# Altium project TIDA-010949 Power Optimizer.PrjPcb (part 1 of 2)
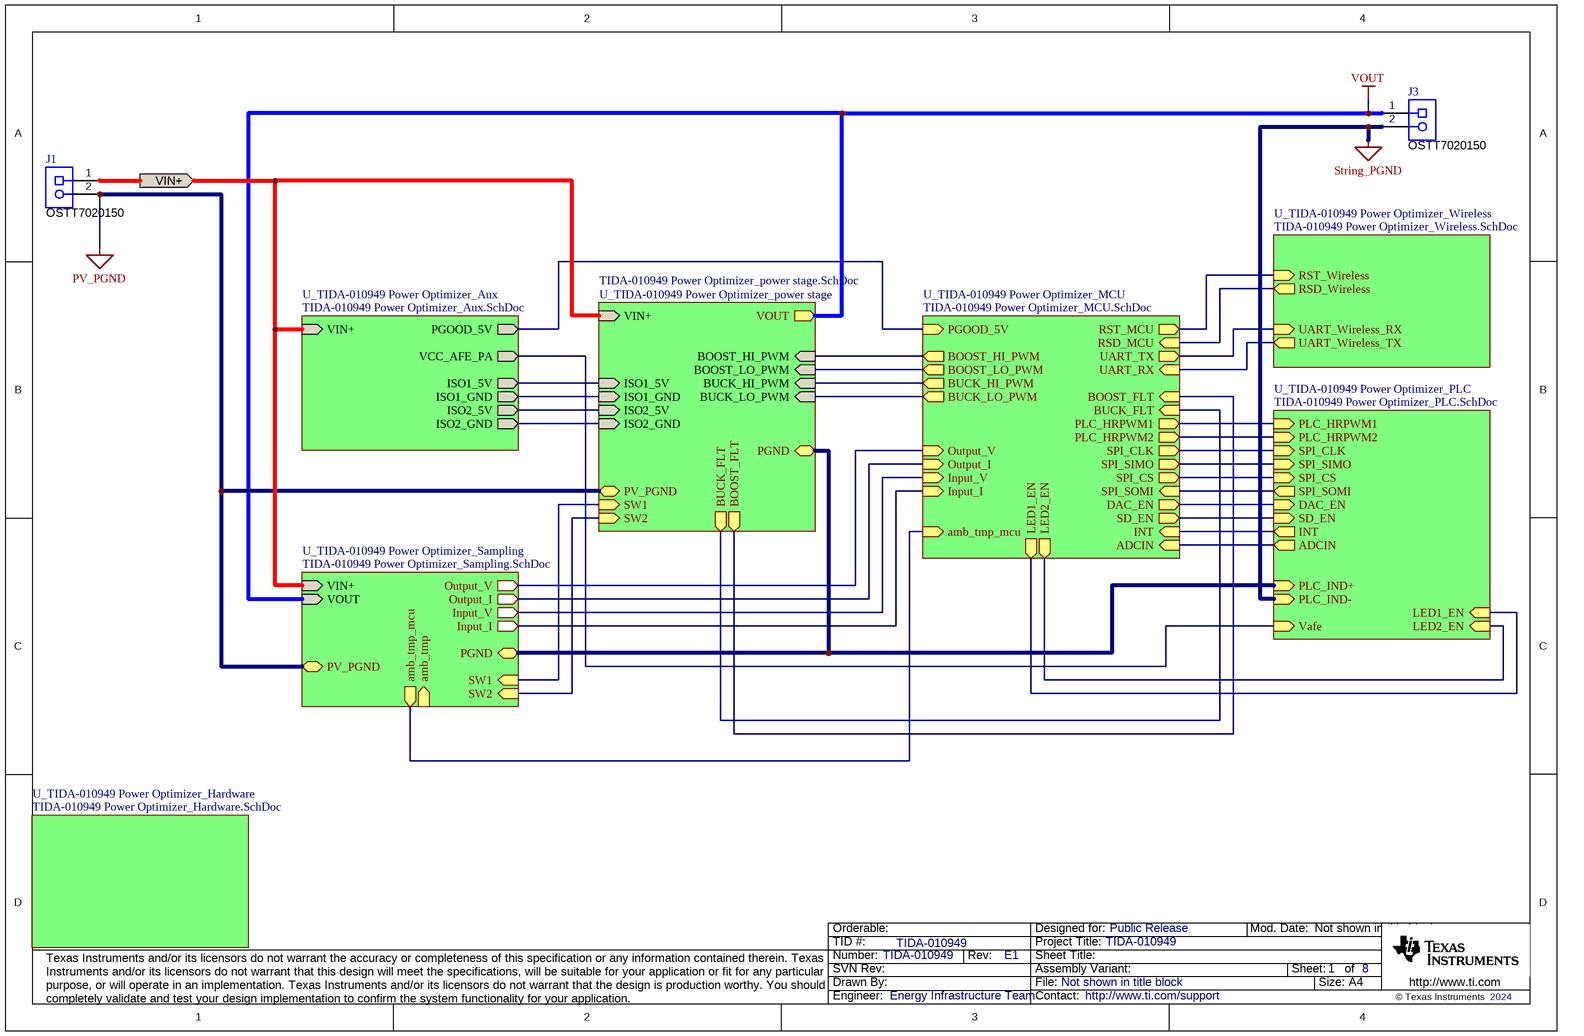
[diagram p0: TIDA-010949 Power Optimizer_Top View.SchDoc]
CopyrightYear: 2024; PCB_Layout: Energy Infrastructure Team; PCB_Rev: E1; PRJ_Customer: Public Release; PRJ_Engineer: Energy Infrastructure Team; PRJ_Number: TIDA-010949; PRJ_Title: TIDA-010949; SCH_Rev: E1; TechSupport: http://www.ti.com/support; TID: TIDA-010949
8 sheets, 266 parts. Net scope: hierarchical (ports join the sheet entries above them; power ports are global).
Board file: TIDA-010949 Power Optimizer.PcbDoc
Sheets:
  TIDA-010949 Power Optimizer_Top View.SchDoc
    U_TIDA-010949 Power Optimizer_Aux = TIDA-010949 Power Optimizer_Aux.SchDoc
    U_TIDA-010949 Power Optimizer_MCU = TIDA-010949 Power Optimizer_MCU.SchDoc
    U_TIDA-010949 Power Optimizer_PLC = TIDA-010949 Power Optimizer_PLC.SchDoc
    U_TIDA-010949 Power Optimizer_Wireless = TIDA-010949 Power Optimizer_Wireless.SchDoc
    U_TIDA-010949 Power Optimizer_Hardware = TIDA-010949 Power Optimizer_Hardware.SchDoc
    U_TIDA-010949 Power Optimizer_Sampling = TIDA-010949 Power Optimizer_Sampling.SchDoc
    U_TIDA-010949 Power Optimizer_power stage = TIDA-010949 Power Optimizer_power stage.SchDoc

## Sheet TIDA-010949 Power Optimizer_Top View.SchDoc
size A4; Date: Not shown in title block; ApprovedBy: Not shown in title block; CheckedBy: Not shown in title block; Author: Not shown in title block; CompanyName: Not shown in title block; Engineer: Not shown in title block; Organization: Not shown in title block; Address1: Not shown in title block; Address2: Not shown in title block; Address3: Not shown in title block; Address4: Not shown in title block; DocumentNumber: 1; Revision: Use project parameter SCH_Rev; SheetNumber: 1; SheetTotal: 8; PageSetup: Record=PageOptions¦CenterHorizontal=True¦CenterVertical=True¦PrintScale=0.93¦XCorrection=1.00¦YCorrection=1.00¦PrintKind=0¦BorderSize=5000000¦LeftOffset=0¦BottomOffset=0¦Orientation=2¦PaperLength=1000¦PaperWidth=1000¦Scale=100¦PaperSource=15¦PrintQuality=600¦MediaType=1¦DitherType=10¦PaperKind=Letter¦PrintScaleMode=1

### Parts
J1  OSTT7020150  [On-Shore_OSTT7020150]
J3  OSTT7020150  [On-Shore_OSTT7020150]

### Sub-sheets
U_TIDA-010949 Power Optimizer_Aux = TIDA-010949 Power Optimizer_Aux.SchDoc: VIN+ (in), PGOOD_5V (out), VCC_AFE_PA (out), ISO1_5V (out), ISO1_GND (out), ISO2_5V (out), ISO2_GND (out)
U_TIDA-010949 Power Optimizer_Hardware = TIDA-010949 Power Optimizer_Hardware.SchDoc: no entries
U_TIDA-010949 Power Optimizer_MCU = TIDA-010949 Power Optimizer_MCU.SchDoc: Output_I (in), Input_I (in), Input_V (in), Output_V (in), PGOOD_5V (in), BUCK_HI_PWM (out), BUCK_LO_PWM (out), BOOST_HI_PWM (out), BOOST_LO_PWM (out), UART_TX (out), PLC_HRPWM1 (out), PLC_HRPWM2 (out), SPI_CLK (out), SPI_SIMO (out), SPI_CS (out), SPI_SOMI (in), DAC_EN (out), SD_EN (out), INT (in), ADCIN (in), LED1_EN (out), LED2_EN (out), UART_RX (in), RSD_MCU (in), RST_MCU (out), amb_tmp_mcu (in), BOOST_FLT (in), BUCK_FLT (in)
U_TIDA-010949 Power Optimizer_PLC = TIDA-010949 Power Optimizer_PLC.SchDoc: SPI_CLK (in), SPI_SIMO (in), SPI_CS (in), DAC_EN (in), SD_EN (in), INT (out), SPI_SOMI (out), ADCIN (out), PLC_HRPWM1 (in), PLC_HRPWM2 (in), PLC_IND+ (in), PLC_IND- (in), Vafe (in), LED1_EN (in), LED2_EN (in)
U_TIDA-010949 Power Optimizer_power stage = TIDA-010949 Power Optimizer_power stage.SchDoc: BUCK_HI_PWM (in), BUCK_LO_PWM (in), BOOST_HI_PWM (in), BOOST_LO_PWM (in), ISO1_5V (in), ISO1_GND (in), ISO2_5V (in), ISO2_GND (in), VIN+ (in), PGND (bidir), PV_PGND (bidir), VOUT (out), SW1 (in), BUCK_FLT (out), BOOST_FLT (out), SW2 (in)
U_TIDA-010949 Power Optimizer_Sampling = TIDA-010949 Power Optimizer_Sampling.SchDoc: Output_I (out), Input_I (out), VIN+ (in), Input_V (out), VOUT (in), Output_V (out), PGND (bidir), PV_PGND (bidir), SW1 (in), amb_tmp_mcu (out), amb_tmp (in), SW2 (in)
U_TIDA-010949 Power Optimizer_Wireless = TIDA-010949 Power Optimizer_Wireless.SchDoc: UART_Wireless_RX (in), UART_Wireless_TX (out), RSD_Wireless (out), RST_Wireless (in)

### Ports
VIN+ (out)

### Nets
PGND: sheet U_TIDA-010949 Power Optimizer_PLC/PLC_IND+, sheet U_TIDA-010949 Power Optimizer_Sampling/PGND, sheet U_TIDA-010949 Power Optimizer_power stage/PGND
PV_PGND: J1.2 ; sheet U_TIDA-010949 Power Optimizer_Sampling/PV_PGND, sheet U_TIDA-010949 Power Optimizer_power stage/PV_PGND
String_PGND: J3.2 ; sheet U_TIDA-010949 Power Optimizer_PLC/PLC_IND-
Vafe: sheet U_TIDA-010949 Power Optimizer_Aux/VCC_AFE_PA, sheet U_TIDA-010949 Power Optimizer_PLC/Vafe
VOUT: J3.1 ; sheet U_TIDA-010949 Power Optimizer_Sampling/VOUT, sheet U_TIDA-010949 Power Optimizer_power stage/VOUT
ADCIN: sheet U_TIDA-010949 Power Optimizer_MCU/ADCIN, sheet U_TIDA-010949 Power Optimizer_PLC/ADCIN
amb_tmp_mcu: sheet U_TIDA-010949 Power Optimizer_MCU/amb_tmp_mcu, sheet U_TIDA-010949 Power Optimizer_Sampling/amb_tmp_mcu
BOOST_FLT: sheet U_TIDA-010949 Power Optimizer_MCU/BOOST_FLT, sheet U_TIDA-010949 Power Optimizer_power stage/BOOST_FLT
BOOST_HI_PWM: sheet U_TIDA-010949 Power Optimizer_MCU/BOOST_HI_PWM, sheet U_TIDA-010949 Power Optimizer_power stage/BOOST_HI_PWM
BOOST_LO_PWM: sheet U_TIDA-010949 Power Optimizer_MCU/BOOST_LO_PWM, sheet U_TIDA-010949 Power Optimizer_power stage/BOOST_LO_PWM
BUCK_FLT: sheet U_TIDA-010949 Power Optimizer_MCU/BUCK_FLT, sheet U_TIDA-010949 Power Optimizer_power stage/BUCK_FLT
BUCK_HI_PWM: sheet U_TIDA-010949 Power Optimizer_MCU/BUCK_HI_PWM, sheet U_TIDA-010949 Power Optimizer_power stage/BUCK_HI_PWM
BUCK_LO_PWM: sheet U_TIDA-010949 Power Optimizer_MCU/BUCK_LO_PWM, sheet U_TIDA-010949 Power Optimizer_power stage/BUCK_LO_PWM
DAC_EN: sheet U_TIDA-010949 Power Optimizer_MCU/DAC_EN, sheet U_TIDA-010949 Power Optimizer_PLC/DAC_EN
Input_I: sheet U_TIDA-010949 Power Optimizer_MCU/Input_I, sheet U_TIDA-010949 Power Optimizer_Sampling/Input_I
Input_V: sheet U_TIDA-010949 Power Optimizer_MCU/Input_V, sheet U_TIDA-010949 Power Optimizer_Sampling/Input_V
INT: sheet U_TIDA-010949 Power Optimizer_MCU/INT, sheet U_TIDA-010949 Power Optimizer_PLC/INT
ISO1_5V: sheet U_TIDA-010949 Power Optimizer_Aux/ISO1_5V, sheet U_TIDA-010949 Power Optimizer_power stage/ISO1_5V
ISO1_GND: sheet U_TIDA-010949 Power Optimizer_Aux/ISO1_GND, sheet U_TIDA-010949 Power Optimizer_power stage/ISO1_GND
ISO2_5V: sheet U_TIDA-010949 Power Optimizer_Aux/ISO2_5V, sheet U_TIDA-010949 Power Optimizer_power stage/ISO2_5V
ISO2_GND: sheet U_TIDA-010949 Power Optimizer_Aux/ISO2_GND, sheet U_TIDA-010949 Power Optimizer_power stage/ISO2_GND
LED1_EN: sheet U_TIDA-010949 Power Optimizer_MCU/LED1_EN, sheet U_TIDA-010949 Power Optimizer_PLC/LED1_EN
LED2_EN: sheet U_TIDA-010949 Power Optimizer_MCU/LED2_EN, sheet U_TIDA-010949 Power Optimizer_PLC/LED2_EN
Output_I: sheet U_TIDA-010949 Power Optimizer_MCU/Output_I, sheet U_TIDA-010949 Power Optimizer_Sampling/Output_I
Output_V: sheet U_TIDA-010949 Power Optimizer_MCU/Output_V, sheet U_TIDA-010949 Power Optimizer_Sampling/Output_V
PGOOD_5V: sheet U_TIDA-010949 Power Optimizer_Aux/PGOOD_5V, sheet U_TIDA-010949 Power Optimizer_MCU/PGOOD_5V
PLC_HRPWM1: sheet U_TIDA-010949 Power Optimizer_MCU/PLC_HRPWM1, sheet U_TIDA-010949 Power Optimizer_PLC/PLC_HRPWM1
PLC_HRPWM2: sheet U_TIDA-010949 Power Optimizer_MCU/PLC_HRPWM2, sheet U_TIDA-010949 Power Optimizer_PLC/PLC_HRPWM2
RSD_MCU: sheet U_TIDA-010949 Power Optimizer_MCU/RSD_MCU, sheet U_TIDA-010949 Power Optimizer_Wireless/RSD_Wireless
RST_MCU: sheet U_TIDA-010949 Power Optimizer_MCU/RST_MCU, sheet U_TIDA-010949 Power Optimizer_Wireless/RST_Wireless
SD_EN: sheet U_TIDA-010949 Power Optimizer_MCU/SD_EN, sheet U_TIDA-010949 Power Optimizer_PLC/SD_EN
SPI_CLK: sheet U_TIDA-010949 Power Optimizer_MCU/SPI_CLK, sheet U_TIDA-010949 Power Optimizer_PLC/SPI_CLK
SPI_CS: sheet U_TIDA-010949 Power Optimizer_MCU/SPI_CS, sheet U_TIDA-010949 Power Optimizer_PLC/SPI_CS
SPI_SIMO: sheet U_TIDA-010949 Power Optimizer_MCU/SPI_SIMO, sheet U_TIDA-010949 Power Optimizer_PLC/SPI_SIMO
SPI_SOMI: sheet U_TIDA-010949 Power Optimizer_MCU/SPI_SOMI, sheet U_TIDA-010949 Power Optimizer_PLC/SPI_SOMI
SW1: sheet U_TIDA-010949 Power Optimizer_Sampling/SW1, sheet U_TIDA-010949 Power Optimizer_power stage/SW1
SW2: sheet U_TIDA-010949 Power Optimizer_Sampling/SW2, sheet U_TIDA-010949 Power Optimizer_power stage/SW2
UART_RX: sheet U_TIDA-010949 Power Optimizer_MCU/UART_RX, sheet U_TIDA-010949 Power Optimizer_Wireless/UART_Wireless_TX
UART_TX: sheet U_TIDA-010949 Power Optimizer_MCU/UART_TX, sheet U_TIDA-010949 Power Optimizer_Wireless/UART_Wireless_RX
VIN+: J1.1 ; port VIN+, sheet U_TIDA-010949 Power Optimizer_Aux/VIN+, sheet U_TIDA-010949 Power Optimizer_Sampling/VIN+, sheet U_TIDA-010949 Power Optimizer_power stage/VIN+

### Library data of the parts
J1 J3 = CMP-0075360-1: Terminal Block, 6.35mm, 2x1, TH; Manufacturer: On-Shore Technology; CNHeader: False; Current_A: 30A; Gender: Female; Cert_CULUS: Y; Voltage_V: 300V; Row_Count: 1; Pitch_mm: 6.35; CT: True

## Sheet TIDA-010949 Power Optimizer_Aux.SchDoc
size A3; Date: Not shown in title block; ApprovedBy: Not shown in title block; CheckedBy: Not shown in title block; Author: Not shown in title block; CompanyName: Not shown in title block; Engineer: Not shown in title block; Organization: Not shown in title block; Address1: Not shown in title block; Address2: Not shown in title block; Address3: Not shown in title block; Address4: Not shown in title block; DocumentNumber: 1; Revision: Use project parameter SCH_Rev; SheetNumber: 3; SheetTotal: 8; PageSetup: Record=PageOptions¦CenterHorizontal=True¦CenterVertical=True¦PrintScale=0.69¦XCorrection=1.00¦YCorrection=1.00¦PrintKind=0¦BorderSize=5000000¦LeftOffset=0¦BottomOffset=0¦Orientation=2¦PaperLength=1000¦PaperWidth=1000¦Scale=100¦PaperSource=15¦PrintQuality=600¦MediaType=1¦DitherType=10¦PaperKind=Letter¦PrintScaleMode=1; SPICEModelCachePKLGOXRY: <root> / <DocumentId>PKLGOXRY</DocumentId> / </root>
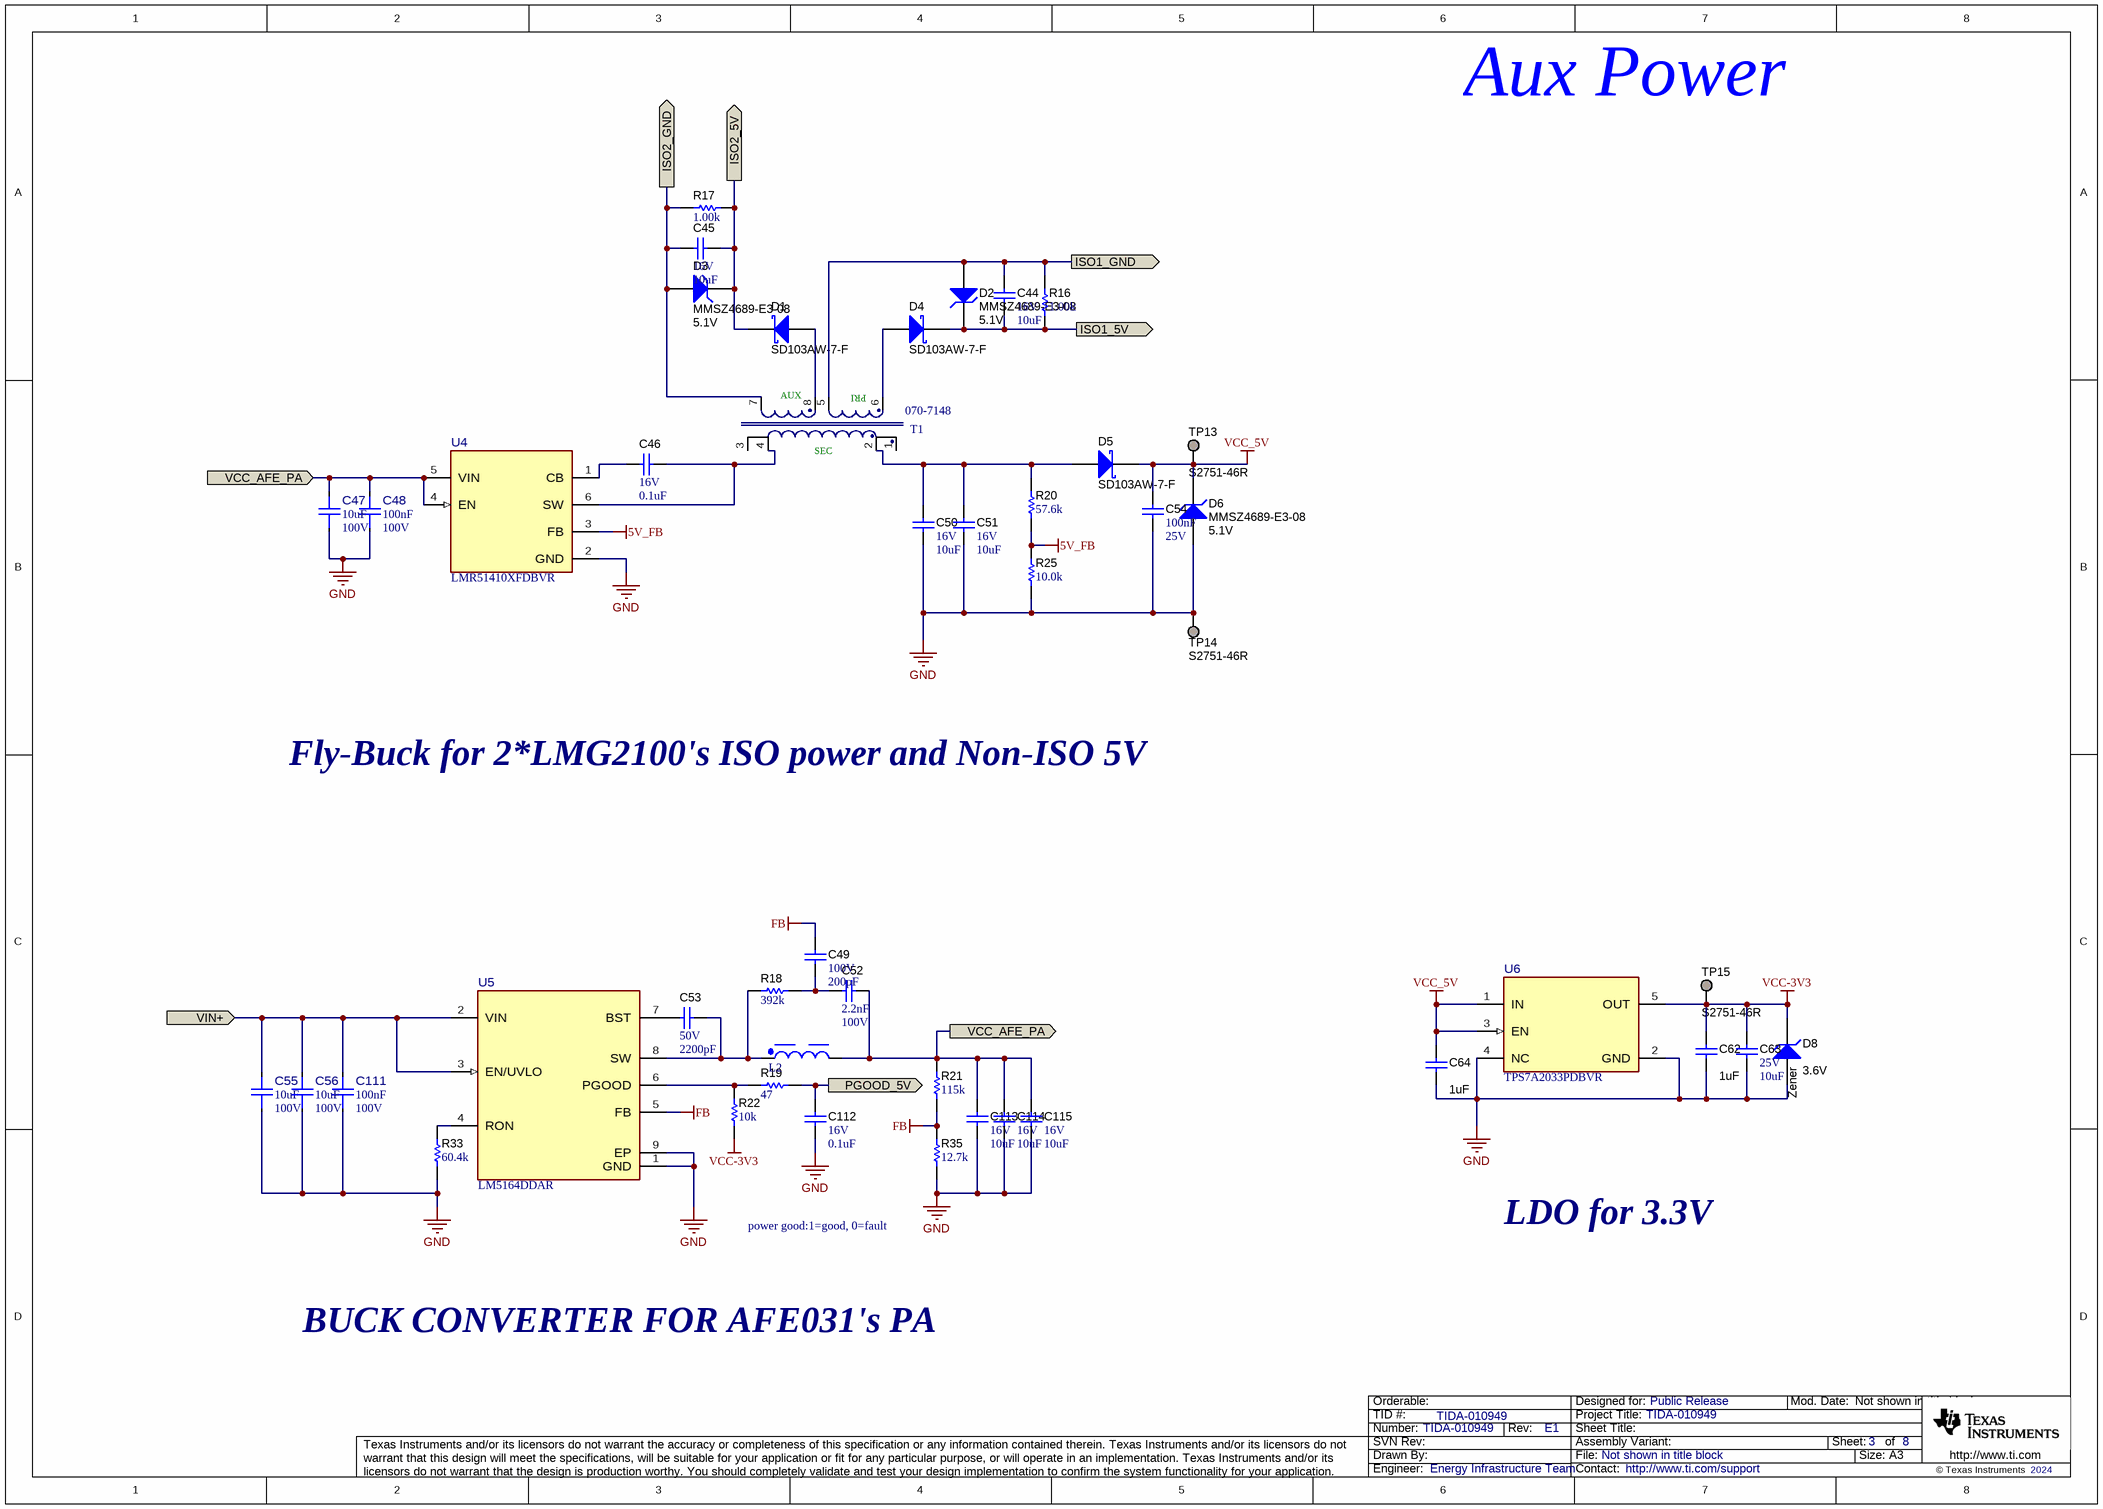
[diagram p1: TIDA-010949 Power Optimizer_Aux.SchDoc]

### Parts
C44  VDC_V: 16V  ValueDisplayed: 10uF  [0805_HV]  (hidden comment: 0805YD106KAT2A)
C45  VDC_V: 16V  ValueDisplayed: 10uF  [0805_HV]  (hidden comment: 0805YD106KAT2A)
C46  VDC_V: 16V  ValueDisplayed: 0.1uF  [0402]  (hidden comment: 0402YC104KAT2A)
C47  ValueDisplayed: 10uF  VDC_V: 100V  [FP-GRM32EC72A106KE05L_1210-MFG]  (hidden comment: GRM32EC72A106KE05L)
C48  Cap_F: 100nF  VDC_V: 100V  [FP-06031C104K4T2A_0603-MFG]  (hidden comment: 06031C104K4T2A)
C49  VDC_V: 100V  ValueDisplayed: 200pF  [0603]  (hidden comment: GRM1885C2A201JA01D)
C50  VDC_V: 16V  ValueDisplayed: 10uF  [0805_HV]  (hidden comment: 0805YD106KAT2A)
C51  VDC_V: 16V  ValueDisplayed: 10uF  [0805_HV]  (hidden comment: 0805YD106KAT2A)
C52  Cap_F: 2.2nF  VDC_V: 100V  [0603]  (hidden comment: GRM188R72A222KA01D)
C53  VDC_V: 50V  ValueDisplayed: 2200pF  [0402]  (hidden comment: GRM155R71H222KA01D)
C54  Cap_F: 100nF  VDC_V: 25V  [0603]  (hidden comment: 06033C104JAT2A)
C55  ValueDisplayed: 10uF  VDC_V: 100V  [FP-GRM32EC72A106KE05L_1210-MFG]  (hidden comment: GRM32EC72A106KE05L)
C56  ValueDisplayed: 10uF  VDC_V: 100V  [FP-GRM32EC72A106KE05L_1210-MFG]  (hidden comment: GRM32EC72A106KE05L)
C62  ValueDisplayed: 1uF  [0603]  (hidden comment: C1608X7R1E105K080AB)
C63  VDC_V: 25V  ValueDisplayed: 10uF  [1206_180]  (hidden comment: GRM31CR71E106KA12L)
C64  ValueDisplayed: 1uF  [0603]  (hidden comment: C1608X7R1E105K080AB)
C111  Cap_F: 100nF  VDC_V: 100V  [FP-06031C104K4T2A_0603-MFG]  (hidden comment: 06031C104K4T2A)
C112  VDC_V: 16V  ValueDisplayed: 0.1uF  [0402S]  (hidden comment: GRM155R71C104JA88D)
C113  VDC_V: 16V  ValueDisplayed: 10uF  [0805_HV]  (hidden comment: 0805YD106KAT2A)
C114  VDC_V: 16V  ValueDisplayed: 10uF  [0805_HV]  (hidden comment: 0805YD106KAT2A)
C115  VDC_V: 16V  ValueDisplayed: 10uF  [0805_HV]  (hidden comment: 0805YD106KAT2A)
D1  SD103AW-7-F  [SOD-123]
D2  MMSZ4689-E3-08  value 5.1V  [SOD-123]
D3  MMSZ4689-E3-08  value 5.1V  [SOD-123]
D4  SD103AW-7-F  [SOD-123]
D5  SD103AW-7-F  [SOD-123]
D6  MMSZ4689-E3-08  value 5.1V  [SOD-123]
D8  Zener  value 3.6V  [SOD-123]
L2  784787680  [WE-PD2SA_7850]  (value not drawn)
R16  ValueDisplayed: 1.00k  [0603]  (hidden comment: RC0603FR-071KL)
R17  ValueDisplayed: 1.00k  [0603]  (hidden comment: RC0603FR-071KL)
R18  ValueDisplayed: 392k  [0402]  (hidden comment: CRCW0402392KFKED)
R19  ValueDisplayed: 47  [0402]  (hidden comment: CRCW040247R0JNED)
R20  ValueDisplayed: 57.6k  [0402]  (hidden comment: CRCW040257K6FKED)
R21  ValueDisplayed: 115k  [0402]  (hidden comment: CRCW0402115KFKED)
R22  ValueDisplayed: 10k  [0402]  (hidden comment: CRCW040210K0JNED)
R25  ValueDisplayed: 10.0k  [0402]  (hidden comment: CRCW040210K0FKED)
R33  ValueDisplayed: 60.4k  [0402]  (hidden comment: CRCW040260K4FKED)
R35  ValueDisplayed: 12.7k  [0402]  (hidden comment: CRCW040212K7FKED)
T1  070-7148  [EP7_7148]
TP13  S2751-46R  [Harwin_S2751-46R]  (no BOM)
TP14  S2751-46R  [Harwin_S2751-46R]  (no BOM)
TP15  S2751-46R  [Harwin_S2751-46R]  (no BOM)
U4  LMR51410XFDBVR  [DBV0006A-MFG]
U5  LM5164DDAR  [DDA0008E-MFG]
U6  TPS7A2033PDBVR  [DBV0005A-MFG]

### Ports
ISO1_5V (out), ISO1_GND (out), ISO2_5V (out), ISO2_GND (out), PGOOD_5V (out), VCC_AFE_PA (in), VCC_AFE_PA (out), VIN+ (in)

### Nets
5V_FB: R20.1 R25.2 U4.3(FB)
FB: C49.1 R21.1 R35.2 U5.5(FB)
GND: C47.1 C48.1 C50.2 C51.2 C54.2 C55.1 C56.1 C62.2 C63.2 C64.2 C111.1 C112.2 C113.2 C114.2 C115.2 D6.2(A) D8.2(A) R25.1 R33.1 R35.1 TP14.1 U4.2(GND) U5.1(GND) U5.9(EP) U6.2(GND) U6.4(NC)
Vafe: C47.2 C48.2 C52.1 C113.1 C114.1 C115.1 L2.2 R21.2 U4.4(EN) U4.5(VIN) ; port VCC_AFE_PA
VCC-3V3: C62.1 C63.1 D8.1(K) R22.2 TP15.1 U6.5(OUT)
VCC_5V: C54.1 C64.1 D5.1(K) D6.1(K) TP13.1 U6.1(IN) U6.3(EN)
ISO1_5V: C44.2 D2.1(K) D4.1(K) R16.2 ; port ISO1_5V
ISO1_GND: C44.1 D2.2(A) R16.1 T1.5 ; port ISO1_GND
ISO2_5V: C45.2 D1.1(K) D3.1(K) R17.2 ; port ISO2_5V
ISO2_GND: C45.1 D3.2(A) R17.1 T1.7 ; port ISO2_GND
PGOOD_5V: C112.1 R19.2 ; port PGOOD_5V
VIN+: C55.2 C56.2 C111.2 U5.2(VIN) U5.3(EN/UVLO) ; port VIN+
NetC46_1: C46.1 T1.4 U4.6(SW)
NetC46_2: C46.2 U4.1(CB)
NetC49_2: C49.2 C52.2 R18.2
NetC50_1: C50.1 C51.1 D5.2(A) R20.2 T1.2
NetC53_1: C53.1 L2.1 R18.1 U5.8(SW)
NetC53_2: C53.2 U5.7(BST)
NetD1_2: D1.2(A) T1.8
NetD4_2: D4.2(A) T1.6
NetR19_1: R19.1 R22.1 U5.6(PGOOD)
NetR33_2: R33.2 U5.4(RON)

Not connected (* = marked no-connect by the designer): T1 1 3

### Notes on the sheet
- Aux Power
- Fly-Buck for 2*LMG2100's ISO power and Non-ISO 5V
- power good:1=good, 0=fault
- LDO for 3.3V
- BUCK CONVERTER FOR AFE031's PA

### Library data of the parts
C44 C45 C50 C51 C113-C115 = CMP-0007677-2: CAP, CERM, 10 uF, 16 V, +/- 10%, X5R, 0805; Manufacturer: AVX; TaMin_C: -55°C; Polarized: N; SizeAreaWB_mm2: 6.75; Value1: Unknown; U/M: EA; Value: 10uF; TaMax_C: 85°C; SizeZ_mm: 1.45; SizeX_mm: 2; SizeY_mm: 1.25; Cap_Case: 0805; SizeArea_mm2: 2.5; Cap_F: 10µF; AEC Category: Q200
C46 = CMP-0006201-2: CAP, CERM, 0.1 uF, 16 V, +/- 10%, X7R, 0402; Manufacturer: AVX; TaMin_C: -55°C; Polarized: N; SizeAreaWB_mm2: 3; Value1: Unknown; U/M: EA; Value: 0.1uF; TaMax_C: 125°C; SizeZ_mm: 0.6; SizeX_mm: 1; SizeY_mm: 0.5; Cap_F: 100nF; AEC Category: Q200
C47 C55 C56 = CMP-0087970-1: 10µF ±10% 100V Ceramic Capacitor X7S 1210 (3225 Metric); Manufacturer: Murata; Symbol Name: SYM-GRM32EC72A106KE05L; Tolerance_%: 0.1; AEC Qualified: No; TempCo: 22%; SizeZ_mm: 2.7mm
C48 C111 = CMP-0094779-1: Cap Ceramic 100nF 100V X7R 10% SMD 0603 125°C Paper T/R; Manufacturer: KYOCERA AVX; AEC Grade: Grade 1; SizeZ_mm: 0.94mm; AEC Qualified: Yes; TempCo: 15%
C49 = CMP-0007254-4: CAP, CERM, 200 pF, 100 V, +/- 5%, C0G/NP0, 0603; Manufacturer: MuRata; TaMin_C: -55°C; Polarized: N; SizeAreaWB_mm2: 4.68; Value1: Unknown; U/M: EA; Value: 200pF; TaMax_C: 125°C; SizeZ_mm: 1; SizeX_mm: 1.6; SizeY_mm: 0.8; SizeArea_mm2: 1.28; AEC Category: Q200
C52 = CMP-0007475-4: CAP, CERM, 2200 pF, 100 V, +/- 10%, X7R, 0603; Manufacturer: MuRata; TaMin_C: -55°C; Polarized: N; SizeAreaWB_mm2: 4.68; Value1: Unknown; U/M: EA; Value: 2200pF; TaMax_C: 125°C; SizeZ_mm: 1; SizeX_mm: 1.6; SizeY_mm: 0.8; SizeArea_mm2: 1.28; AEC Category: Q200
C53 = CMP-0006683-2: CAP, CERM, 2200 pF, 50 V, +/- 10%, X7R, 0402; Manufacturer: MuRata; TaMin_C: -55°C; Polarized: N; SizeAreaWB_mm2: 3; Value1: Unknown; U/M: EA; Value: 2200pF; TaMax_C: 125°C; SizeZ_mm: 0.6; SizeX_mm: 1; SizeY_mm: 0.5; Cap_F: 2.2nF; AEC Category: Q200
C54 = CMP-0006752-5: CAP, CERM, 0.1 uF, 25 V, +/- 5%, X7R, 0603; Manufacturer: AVX; TaMin_C: -55°C; ESR_ohm: 0.05; Polarized: N; SizeAreaWB_mm2: 4.68; Value1: 0.05 ohm; U/M: EA; Value: 0.1uF; TaMax_C: 125°C; SizeZ_mm: 1; SizeX_mm: 1.6; SizeY_mm: 0.8; SizeArea_mm2: 1.28; AEC Category: Q200
C62 C64 = CMP-0006831-4: CAP CER 1UF 16V Y5V 0603; Manufacturer: Yageo; PartNumber: CC0603MRY5V7BB105; TaMin_C: -55°C; Polarized: N; TempCo: X7R; SizeAreaWB_mm2: 4.68; Value1: Unknown; U/M: EA; TaMax_C: 125°C; Tolerance_%: 10%; SizeZ_mm: 1; SizeX_mm: 1.6; SizeY_mm: 0.8; SizeArea_mm2: 1.28; CompType: Capacitor; Cap_F: 1µF; AEC Category: Q200
C63 = CMP-0008965-2: CAP, CERM, 10 uF, 25 V, +/- 10%, X7R, 1206; Manufacturer: MuRata; TaMin_C: -55°C; Polarized: N; SizeAreaWB_mm2: 10.92; Value1: Unknown; U/M: EA; Value: 10uF; TaMax_C: 125°C; SizeZ_mm: 1.8; SizeX_mm: 3.2; SizeY_mm: 1.6; Cap_Case: 2220; SizeArea_mm2: 5.12; Cap_F: 10µF; AEC Category: Q200
C112 = CMP-0006640-2: CAP, CERM, 0.1 uF, 16 V, +/- 5%, X7R, 0402; Manufacturer: MuRata; TaMin_C: -55°C; Polarized: N; SizeAreaWB_mm2: 3; Value1: Unknown; U/M: EA; Value: 0.1uF; TaMax_C: 125°C; SizeZ_mm: 0.6; SizeX_mm: 1; SizeY_mm: 0.5; Cap_Case: 0402; Cap_F: 100nF; AEC Category: Q200
D1 D4 D5 = CMP-0028543-2: Diode, Schottky, 40 V, 0.35 A, SOD-123; Manufacturer: Diodes Inc.; AEC Category: Q101; Io_A: 350mA; SizeZ_mm: 1.35; Vf_V: 550mV; Green_REACh: Passed; SizeAreaWB_mm2: 13.095; SizeY_mm: 1.7; SizeX_mm: 3.85; Value2: 0.55V; Green_Lifecycle: Active; Vr_V: 40V; Value1: 0.35A; SizeArea_mm2: 6.545; Value: 40V
D2 D3 D6 = CMP-0077599-3: Diode, Zener, 5.1 V, 500 mW, SOD-123; Manufacturer: Vishay-Semiconductor; AEC Category: Q101; SizeAreaWB_mm2: 13.095; SizeY_mm: 1.7; SizeArea_mm2: 6.545; SizeX_mm: 3.85; AEC Qualified: N; SizeZ_mm: 1.35; RJA_CperW: 340; Power_W: 500mW; Value1: 0.5W
D8 = CMP-0005782-1: Diode, Zener, 3.6 V, 500 mW, SOD-123; PartNumber: MMSZ4685T1G; Manufacturer: ON Semiconductor; U/M: EA; Power_W: 500mW; Value1: 0.5W; RJA_CperW: 340; SizeAreaWB_mm2: 13.095; SizeArea_mm2: 6.545; SizeX_mm: 3.85; SizeY_mm: 1.7; SizeZ_mm: 1.35; AEC Category: Q101
L2 = CMP-0102060-1: WE-PD2SA SMT Power Inductor, size 7850, 68uH, 1.12A, 290mOhm; Manufacturer: Wurth Elektronik; Case/Size Code: 7850; DC Resistance: 246mOhm; Saturation Current: 1A; Self Resonant Frequency: 7.5MHz
R16 R17 = CMP-0022895-5: RES, 1.00 k, 1%, 0.1 W, 0603; Manufacturer: Yageo; Power_W: 100mW; TempCo: 100 ppm/C; Value_Code: 1k00; Value: 1.00k; EIA_Code: E96; Res_ohm: 1k; SizeX_mm: 1.6; SizeY_mm: 0.8; SizeZ_mm: 1; Value2: 0.1W; SizeArea_mm2: 1.28; AEC Qualified: N; VDC_V: 75V; AEC Category: Q200; SizeAreaWB_mm2: 4.68
R18 = CMP-0026325-2: RES, 392 k, 1%, 0.063 W, AEC-Q200 Grade 0, 0402; Manufacturer: Vishay-Dale; Power_W: 63mW; TempCo: 100 ppm/C; Value: 392k; EIA_Code: E96; SizeX_mm: 1; SizeY_mm: 0.5; SizeZ_mm: 0.6; Value2: 0.063W; AEC Qualified: Y; VDC_V: 50V; AEC Category: Q200; AEC Grade: 0
R19 = CMP-0026936-3: RES, 47, 5%, 0.063 W, AEC-Q200 Grade 0, 0402; Manufacturer: Vishay-Dale; Power_W: 63mW; TempCo: 200 ppm/C; Value_Code: 47R0; Value: 47; EIA_Code: E24; SizeX_mm: 1; SizeY_mm: 0.5; SizeZ_mm: 0.6; Value2: 0.063W; AEC Qualified: Y; VDC_V: 50V; AEC Category: Q200; AEC Grade: 0
R20 = CMP-0026457-2: RES, 57.6 k, 1%, 0.063 W, AEC-Q200 Grade 0, 0402; Manufacturer: Vishay-Dale; Power_W: 63mW; TempCo: 100 ppm/C; Value_Code: 57k6; Value: 57.6k; EIA_Code: E96; SizeX_mm: 1; SizeY_mm: 0.5; SizeZ_mm: 0.6; Value2: 0.063W; AEC Qualified: Y; VDC_V: 50V; AEC Category: Q200; AEC Grade: 0
R21 = CMP-0025971-3: RES, 115 k, 1%, 0.063 W, AEC-Q200 Grade 0, 0402; Manufacturer: Vishay-Dale; Power_W: 63mW; TempCo: 100 ppm/C; Value: 115k; EIA_Code: E96; SizeX_mm: 1; SizeY_mm: 0.5; SizeZ_mm: 0.6; Value2: 0.063W; AEC Qualified: Y; VDC_V: 50V; AEC Category: Q200; AEC Grade: 0
R22 = CMP-0026825-5: RES, 10 k, 5%, 0.063 W, AEC-Q200 Grade 0, 0402; Manufacturer: Vishay-Dale; Power_W: 63mW; TempCo: 200 ppm/C; Value_Code: 10k0; Value: 10k; EIA_Code: E24; SizeX_mm: 1; SizeY_mm: 0.5; SizeZ_mm: 0.6; Value2: 0.063W; AEC Qualified: Y; VDC_V: 50V; AEC Category: Q200; AEC Grade: 0
R25 = CMP-0025958-3: RES, 10.0 k, 1%, 0.063 W, AEC-Q200 Grade 0, 0402; Manufacturer: Vishay-Dale; Power_W: 63mW; TempCo: 100 ppm/C; Value_Code: 10k0; Value: 10.0k; EIA_Code: E96; Res_ohm: 10k; SizeX_mm: 1; SizeY_mm: 0.5; SizeZ_mm: 0.6; Value2: 0.063W; AEC Qualified: Y; VDC_V: 50V; AEC Category: Q200; AEC Grade: 0
R33 = CMP-0026486-2: RES, 60.4 k, 1%, 0.063 W, AEC-Q200 Grade 0, 0402; Manufacturer: Vishay-Dale; Power_W: 63mW; TempCo: 100 ppm/C; Value_Code: 60k4; Value: 60.4k; EIA_Code: E96; SizeX_mm: 1; SizeY_mm: 0.5; SizeZ_mm: 0.6; Value2: 0.063W; AEC Qualified: Y; VDC_V: 50V; AEC Category: Q200; AEC Grade: 0
R35 = CMP-0025993-3: RES, 12.7 k, 1%, 0.063 W, AEC-Q200 Grade 0, 0402; Manufacturer: Vishay-Dale; Power_W: 63mW; TempCo: 100 ppm/C; Value_Code: 12k7; Value: 12.7k; EIA_Code: E96; SizeX_mm: 1; SizeY_mm: 0.5; SizeZ_mm: 0.6; Value2: 0.063W; AEC Qualified: Y; VDC_V: 50V; AEC Category: Q200; AEC Grade: 0
T1 = EP7, 070-7148: EP7 8-Term., SMT, Horizontal; Manufacturer: Würth Elektronik Midcom; Core: Power: 150-2365, Digital: 150-0341
TP13-TP15 = CMP-0003968-1: Test Point, SMT; Manufacturer: Harwin
U4 = CMP-0121876-1: SIMPLE SWITCHER® Power Converter, 4-V to 42-V, 1-A Buck Converter, SOT23; Manufacturer: Texas Instruments; SizeZ_mm: 1.45mm; AEC Qualified: No; AEC Grade: NA; Max Duty Cycle: 98%; Max Supply Voltage: 42V; Min Supply Voltage: 4V; Nominal Supply Current: 26.5-420uA; Number Of Outputs: 1; Output Type: AdjustableProgrammable; Output Voltage: 0.8-28V; Standoff Height: 0mm; Switching Frequency: 400kHz; TJmax_C: +150°C
U5 = CMP-0089262-2: Buck Switching Regulator IC Positive Adjustable 1.2V 1 Output 1A 8-PowerSOIC (0.154", 3.90mm Width); Manufacturer: Texas Instruments; AEC Qualified: No; Standoff Height: 0mm; AEC Category: Q200; Max Duty Cycle: 99%; Nominal Supply Current: 600uA; Max Supply Voltage: 100V; Number Of Outputs: 1; Switching Frequency: 1MHz; Output Type: AdjustableProgrammable; Min Supply Voltage: 6V; Output Voltage: 1.2-90V; TJmax_C: +150°C
U6 = CMP-0092532-1: 300-mA, Ultra-Low-Noise, Low-IQ, High PSRR LDO; Manufacturer: Texas Instruments; TJmax_C: +125°C; Min Supply Voltage: 1.6V; SizeZ_mm: 1.45mm; Output Voltage: 3.3V; Number Of Outputs: 1; Nominal Supply Current: 6.5uA; AEC Qualified: No; Accuracy Percentage: 1.5%; Max Supply Voltage: 6V; Dropout Voltage: 145mV; Standoff Height: 0mm; Output Type: Fixed

## Sheet TIDA-010949 Power Optimizer_MCU.SchDoc
size A3; Date: Not shown in title block; ApprovedBy: Not shown in title block; CheckedBy: Not shown in title block; Author: Not shown in title block; CompanyName: Not shown in title block; Engineer: Not shown in title block; Organization: Not shown in title block; Address1: Not shown in title block; Address2: Not shown in title block; Address3: Not shown in title block; Address4: Not shown in title block; DocumentNumber: 1; Revision: Use project parameter SCH_Rev; SheetNumber: 4; SheetTotal: 8; PageSetup: Record=PageOptions¦CenterHorizontal=True¦CenterVertical=True¦PrintScale=0.69¦XCorrection=1.00¦YCorrection=1.00¦PrintKind=0¦BorderSize=5000000¦LeftOffset=0¦BottomOffset=0¦Orientation=2¦PaperLength=1000¦PaperWidth=1000¦Scale=100¦PaperSource=15¦PrintQuality=600¦MediaType=1¦DitherType=10¦PaperKind=Letter¦PrintScaleMode=1
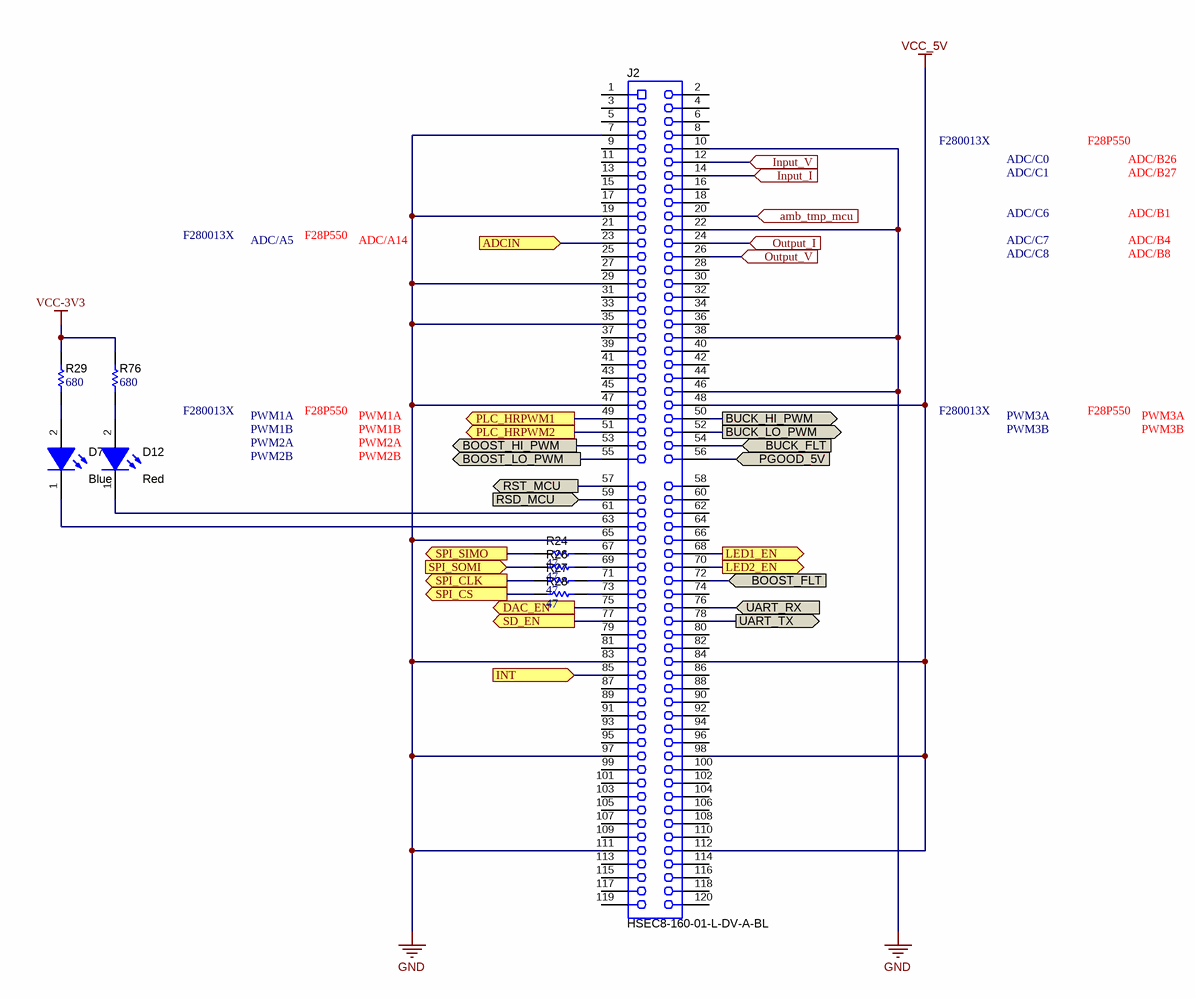
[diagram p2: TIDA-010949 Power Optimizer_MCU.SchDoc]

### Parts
D7  value Blue  [WL-SMCW_Blue]  (hidden comment: 150060BS75000)
D12  value Red  [WL-SMCW_RED]  (hidden comment: 150060RS75000)
J2  HSEC8-160-01-L-DV-A-BL  [controlCARD-120HSEC]
R24  ValueDisplayed: 47  [0402]  (hidden comment: CRCW040247R0JNED)
R26  ValueDisplayed: 47  [0402]  (hidden comment: CRCW040247R0JNED)
R27  ValueDisplayed: 47  [0402]  (hidden comment: CRCW040247R0JNED)
R28  ValueDisplayed: 47  [0402]  (hidden comment: CRCW040247R0JNED)
R29  ValueDisplayed: 680  [0603S]  (hidden comment: RC0603JR-07680RL)
R76  ValueDisplayed: 680  [0603S]  (hidden comment: RC0603JR-07680RL)

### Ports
ADCIN (in), amb_tmp_mcu (in), BOOST_FLT (in), BOOST_HI_PWM (out), BOOST_LO_PWM (out), BUCK_FLT (in), BUCK_HI_PWM (out), BUCK_LO_PWM (out), DAC_EN (out), Input_I (in), Input_V (in), INT (in), LED1_EN (out), LED2_EN (out), Output_I (in), Output_V (in), PGOOD_5V (in), PLC_HRPWM1 (out), PLC_HRPWM2 (out), RSD_MCU (in), RST_MCU (out), SD_EN (out), SPI_CLK (out), SPI_CS (out), SPI_SIMO (out), SPI_SOMI (in), UART_RX (in), UART_TX (out)

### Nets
GND: J2.7 J2.10 J2.19 J2.22 J2.29 J2.35 J2.38 J2.46 J2.47 J2.65 J2.83 J2.97 J2.111
VCC-3V3: R29.2 R76.2
VCC_5V: J2.48 J2.84 J2.98 J2.112
ADCIN: J2.23 ; port ADCIN
amb_tmp_mcu: J2.20 ; port amb_tmp_mcu
BOOST_FLT: J2.72 ; port BOOST_FLT
BOOST_HI_PWM: J2.53 ; port BOOST_HI_PWM
BOOST_LO_PWM: J2.55 ; port BOOST_LO_PWM
BUCK_FLT: J2.54 ; port BUCK_FLT
BUCK_HI_PWM: J2.50 ; port BUCK_HI_PWM
BUCK_LO_PWM: J2.52 ; port BUCK_LO_PWM
DAC_EN: J2.75 ; port DAC_EN
Input_I: J2.14 ; port Input_I
Input_V: J2.12 ; port Input_V
INT: J2.85 ; port INT
LED1_EN: J2.68 ; port LED1_EN
LED2_EN: J2.70 ; port LED2_EN
Output_I: J2.24 ; port Output_I
Output_V: J2.26 ; port Output_V
PGOOD_5V: J2.56 ; port PGOOD_5V
PLC_HRPWM1: J2.49 ; port PLC_HRPWM1
PLC_HRPWM2: J2.51 ; port PLC_HRPWM2
RSD_MCU: J2.59 ; port RSD_MCU
RST_MCU: J2.57 ; port RST_MCU
SD_EN: J2.77 ; port SD_EN
SPI_CLK: R27.1 ; port SPI_CLK
SPI_CS: R28.1 ; port SPI_CS
SPI_SIMO: R24.1 ; port SPI_SIMO
SPI_SOMI: R26.1 ; port SPI_SOMI
UART_RX: J2.76 ; port UART_RX
UART_TX: J2.78 ; port UART_TX
NetD7_1: D7.1(K) J2.63
NetD7_2: D7.2(A) R29.1
NetD12_1: D12.1(K) J2.61
NetD12_2: D12.2(A) R76.1
NetJ2_67: J2.67 R24.2
NetJ2_69: J2.69 R26.2
NetJ2_71: J2.71 R27.2
NetJ2_73: J2.73 R28.2

Not connected (* = marked no-connect by the designer): J2 1 2 3 4 5 6 8 9 11 13 15 16 17 18 21 25 27 28 30 31 32 33 34 36 37 39 40 41 42 43 44 45 58 60 62 64 66 74 79 80 81 82 86 87 88 89 90 91 92 93 94 95 96 99 100 101 102 103 104 105 106 107 108 109 110 113 114 115 116 117 118 119 120

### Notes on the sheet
- F280013X
- ADC/C0
- ADC/C1
- F28P550
- ADC/B26
- ADC/B27
- ADC/A5
- ADC/A14
- ADC/C8
- ADC/C7
- ADC/C6
- ADC/B8
- ADC/B4
- ADC/B1
- PWM1A
- PWM1B
- PWM2A
- PWM2B
- PWM3A
- PWM3B

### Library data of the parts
D7 = CMP-0002946-3: LED, Blue, SMD; Manufacturer: Wurth Elektronik; Power_TotalModule: 105mW; Angle: 140; Tjmax_C: 85°C; Vf_V: 3.2V; Io_A: 30mA; Value1: 0.105W; Vr_V: 5V; Type: InGaN
D12 = CMP-0002947-3: LED, Red, SMD; Manufacturer: Wurth Elektronik; Value1: 0.072W; Vf_V: 2V; Angle: 140; Tjmax_C: 85°C; Type: AlInGaP; Vr_V: 5V; Io_A: 30mA; Power_TotalModule: 72mW
J2 = CMP-0003814-2: C2000 controlCARD-120HSEC connector, SMT; Manufacturer: Samtec; Note: The pin numbering does not match Samtec datasheet
R24 R26-R28 = CMP-0026936-3: as R19 on sheet TIDA-010949 Power Optimizer_Aux
R29 R76 = CMP-0025936-5: RES, 680, 5%, 0.1 W, 0603; Manufacturer: Yageo; Power_W: 100mW; TempCo: 100 ppm/C; Value_Code: 680R; Value: 680; EIA_Code: E24; SizeX_mm: 1.6; SizeY_mm: 0.8; SizeZ_mm: 1; Value2: 0.1W; SizeArea_mm2: 1.28; AEC Qualified: N; VDC_V: 75V; AEC Category: Q200; SizeAreaWB_mm2: 4.68

## Sheet TIDA-010949 Power Optimizer_PLC.SchDoc
size A3; Date: Not shown in title block; ApprovedBy: Not shown in title block; CheckedBy: Not shown in title block; Author: Not shown in title block; CompanyName: Not shown in title block; Engineer: Not shown in title block; Organization: Not shown in title block; Address1: Not shown in title block; Address2: Not shown in title block; Address3: Not shown in title block; Address4: Not shown in title block; DocumentNumber: 1; Revision: Use project parameter SCH_Rev; SheetNumber: 5; SheetTotal: 8; PageSetup: Record=PageOptions¦CenterHorizontal=True¦CenterVertical=True¦PrintScale=0.93¦XCorrection=1.00¦YCorrection=1.00¦PrintKind=0¦BorderSize=5000000¦LeftOffset=0¦BottomOffset=0¦Orientation=2¦PaperLength=1000¦PaperWidth=1000¦Scale=100¦PaperSource=15¦PrintQuality=600¦MediaType=1¦DitherType=10¦PaperKind=Letter¦PrintScaleMode=1
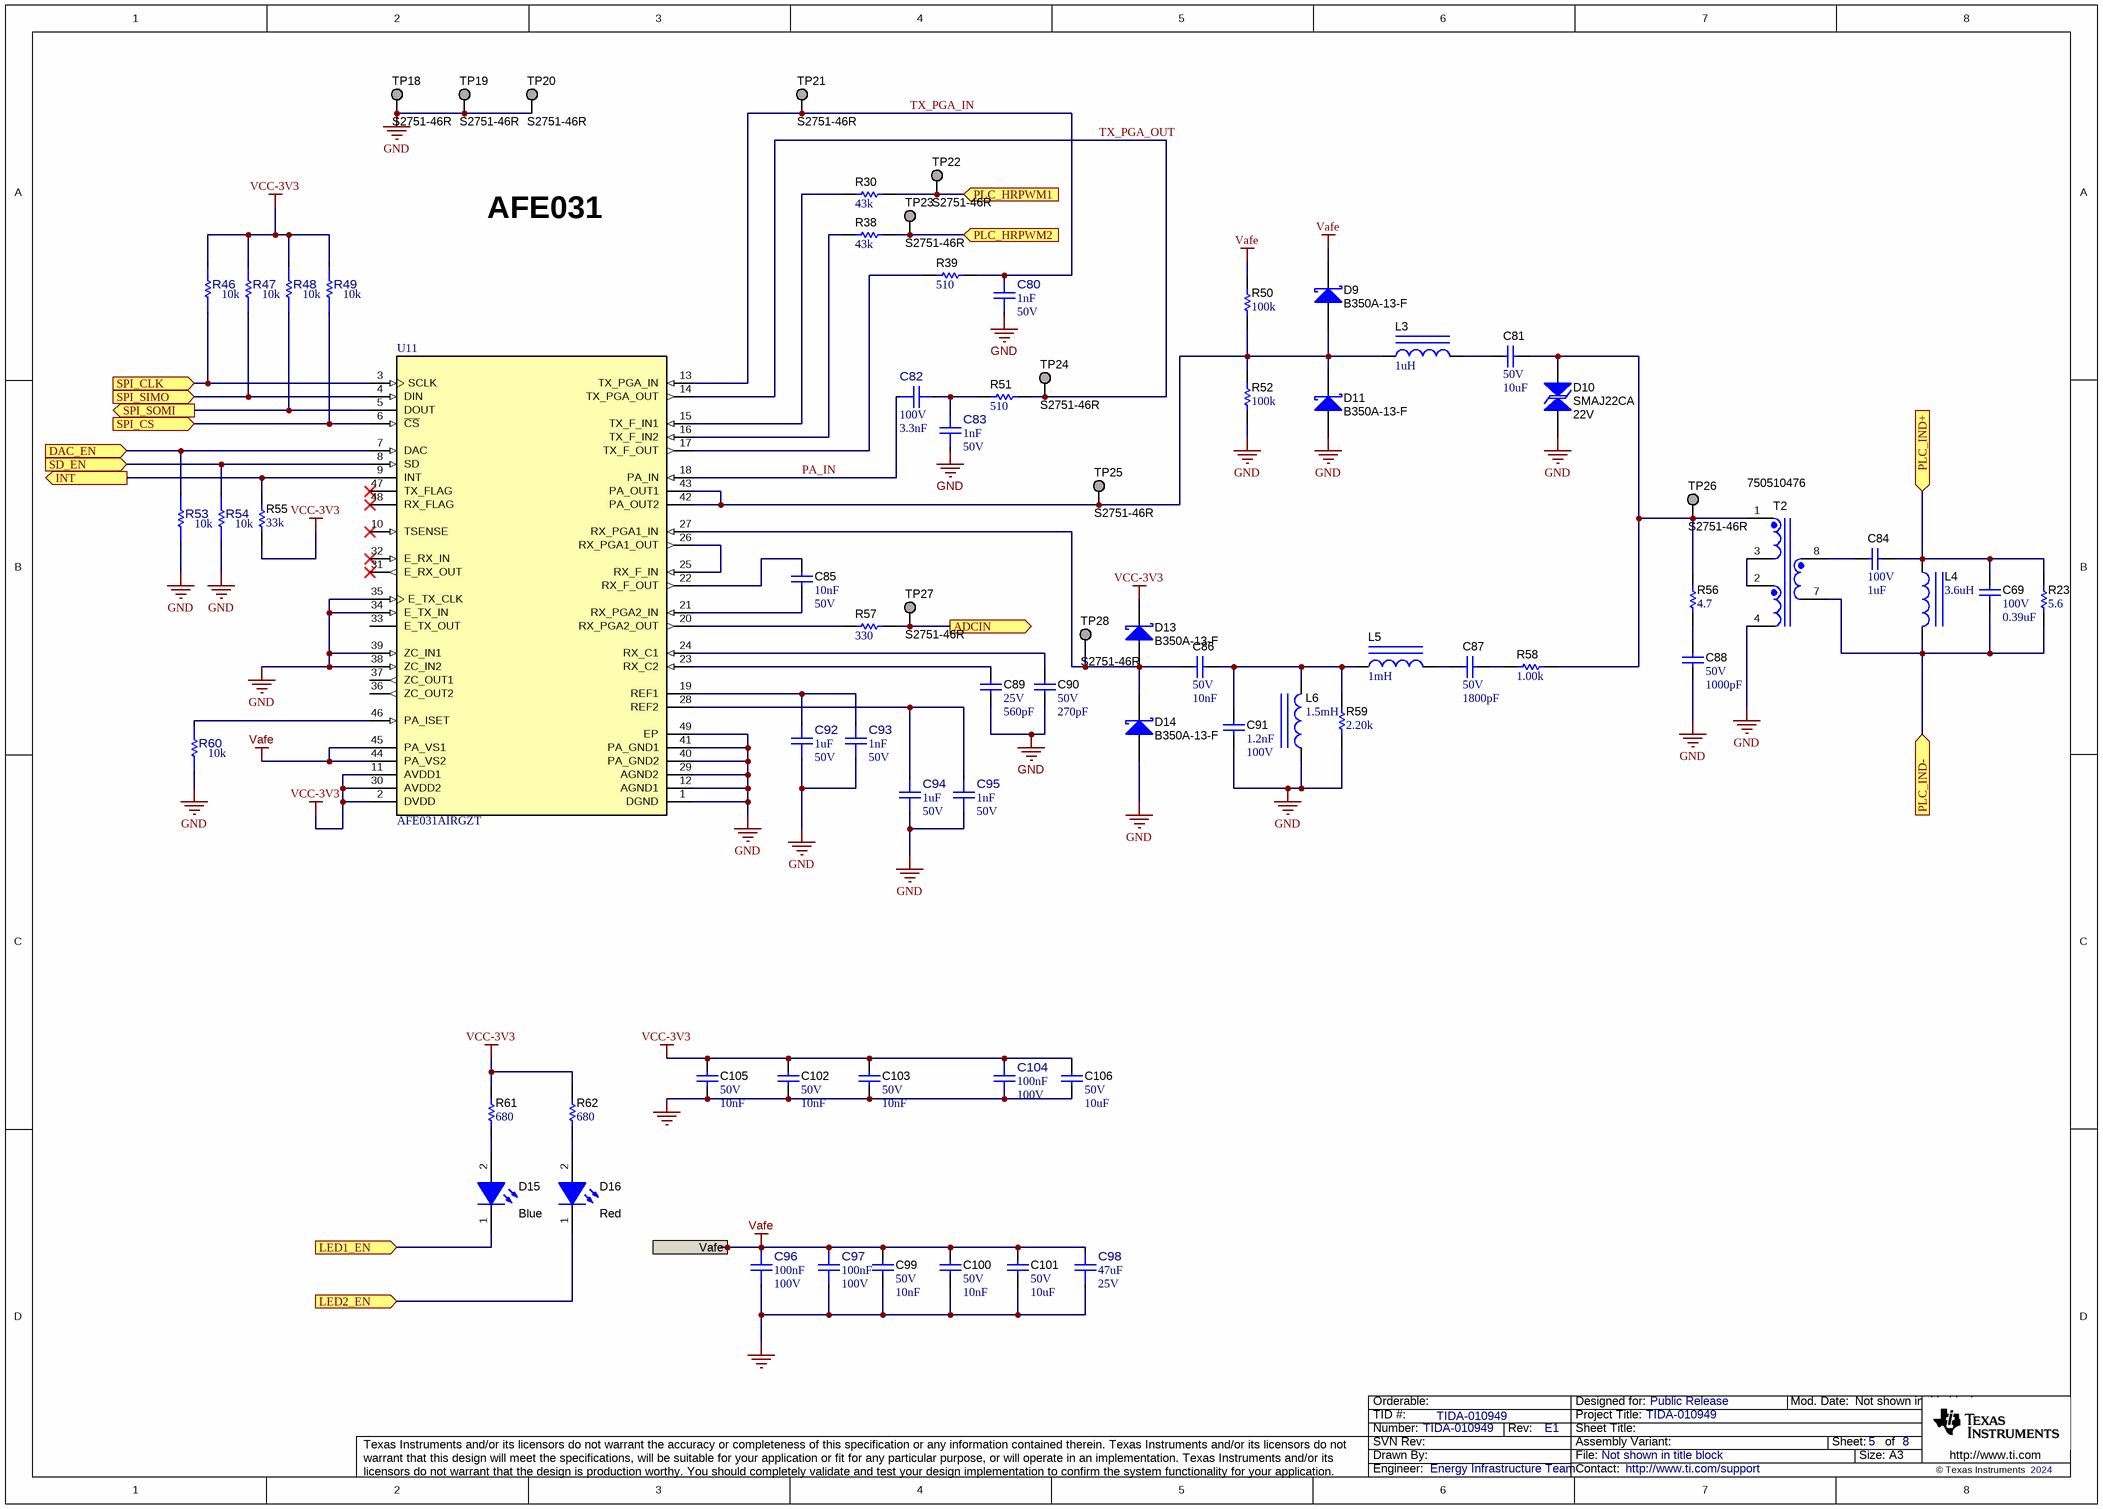
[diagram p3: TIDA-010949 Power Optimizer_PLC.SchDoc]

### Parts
C69  VDC_V: 100V  ValueDisplayed: 0.39uF  [1206]  (hidden comment: C1206C394K1RAC7800)
C80  Cap_F: 1nF  VDC_V: 50V  [FP-C0603X102K5RAC7867_0603-MFG]  (hidden comment: C0603X102K5RAC7867)
C81  VDC_V: 50V  ValueDisplayed: 10uF  [1206_180]  (hidden comment: GRT31CR61H106KE01L)
C82  VDC_V: 100V  Cap_F: 3.3nF  [FP-06031C332J4Z2A_0603-MFG]  (hidden comment: 06031C332J4Z2A)
C83  Cap_F: 1nF  VDC_V: 50V  [FP-C0603X102K5RAC7867_0603-MFG]  (hidden comment: C0603X102K5RAC7867)
C84  VDC_V: 100V  ValueDisplayed: 1uF  [1206_180]  (hidden comment: CGA5L2X7R2A105K160AA)
C85  Cap_F: 10nF  VDC_V: 50V  [0603S]  (hidden comment: GRM188R71H103KA01D)
C86  VDC_V: 50V  Cap_F: 10nF  [0603S]  (hidden comment: 885012206089)
C87  VDC_V: 50V  ValueDisplayed: 1800pF  [0603S]  (hidden comment: GRM1885C1H182JA01D)
C88  VDC_V: 50V  ValueDisplayed: 1000pF  [0603S]  (hidden comment: 06035A102KAT2A)
C89  VDC_V: 25V  ValueDisplayed: 560pF  [0603S]  (hidden comment: GRM1885C1E561JA01D)
C90  VDC_V: 50V  ValueDisplayed: 270pF  [0603S]  (hidden comment: GRM1885C1H271JA01D)
C91  Cap_F: 1.2nF  VDC_V: 100V  [0603S]  (hidden comment: 06031C122JAT2A)
C92  ValueDisplayed: 1uF  VDC_V: 50V  [FP-GCM188D71H105KE36J_0603-MFG]  (hidden comment: GCM188D71H105KE36J)
C93  Cap_F: 1nF  VDC_V: 50V  [FP-C0603X102K5RAC7867_0603-MFG]  (hidden comment: C0603X102K5RAC7867)
C94  ValueDisplayed: 1uF  VDC_V: 50V  [FP-GCM188D71H105KE36J_0603-MFG]  (hidden comment: GCM188D71H105KE36J)
C95  Cap_F: 1nF  VDC_V: 50V  [FP-C0603X102K5RAC7867_0603-MFG]  (hidden comment: C0603X102K5RAC7867)
C96  Cap_F: 100nF  VDC_V: 100V  [FP-06031C104K4T2A_0603-MFG]  (hidden comment: 06031C104K4T2A)
C97  Cap_F: 100nF  VDC_V: 100V  [FP-06031C104K4T2A_0603-MFG]  (hidden comment: 06031C104K4T2A)
C98  ValueDisplayed: 47uF  VDC_V: 25V  [FP-CGA9N3X7R1E476M230KB_2220-MFG]  (hidden comment: CGA9N3X7R1E476M230KB)
C99  VDC_V: 50V  Cap_F: 10nF  [0603S]  (hidden comment: 885012206089)
C100  VDC_V: 50V  Cap_F: 10nF  [0603S]  (hidden comment: 885012206089)
C101  VDC_V: 50V  ValueDisplayed: 10uF  [1206_180]  (hidden comment: GRT31CR61H106KE01L)
C102  VDC_V: 50V  Cap_F: 10nF  [0603S]  (hidden comment: 885012206089)
C103  VDC_V: 50V  Cap_F: 10nF  [0603S]  (hidden comment: 885012206089)
C104  Cap_F: 100nF  VDC_V: 100V  [FP-06031C104K4T2A_0603-MFG]  (hidden comment: 06031C104K4T2A)
C105  VDC_V: 50V  Cap_F: 10nF  [0603S]  (hidden comment: 885012206089)
C106  VDC_V: 50V  ValueDisplayed: 10uF  [1206_180]  (hidden comment: GRT31CR61H106KE01L)
D9  B350A-13-F  [SMA]
D10  SMAJ22CA  value 22V  [SMA_Bi]
D11  B350A-13-F  [SMA]
D13  B350A-13-F  [SMA]
D14  B350A-13-F  [SMA]
D15  value Blue  [WL-SMCW_Blue]  (hidden comment: 150060BS75000)
D16  value Red  [WL-SMCW_RED]  (hidden comment: 150060RS75000)
L3  ValueDisplayed: 1uH  [LQH2MC_52]  (hidden comment: LQH2MCN1R0M52)
L4  ValueDisplayed: 3.6uH  [SER2013]  (hidden comment: SER2013-362MLB)
L5  ValueDisplayed: 1mH  [DO1607B]  (hidden comment: DO1607B-105MLB)
L6  ValueDisplayed: 1.5mH  [DO1607B]  (hidden comment: DO1607B-155MLB)
R23  ValueDisplayed: 5.6  [1210]  (hidden comment: RC1210JR-075R6L)
R30  ValueDisplayed: 43k  [0603S]  (hidden comment: RC0603JR-0743KL)
R38  ValueDisplayed: 43k  [0603S]  (hidden comment: RC0603JR-0743KL)
R39  ValueDisplayed: 510  [0603S]  (hidden comment: RC0603JR-07510RL)
R46  value 10k  [FP-CRCW060310K0JNEBC_0603-MFG]  (hidden comment: CRCW060310K0JNEBC)
R47  value 10k  [FP-CRCW060310K0JNEBC_0603-MFG]  (hidden comment: CRCW060310K0JNEBC)
R48  value 10k  [FP-CRCW060310K0JNEBC_0603-MFG]  (hidden comment: CRCW060310K0JNEBC)
R49  value 10k  [FP-CRCW060310K0JNEBC_0603-MFG]  (hidden comment: CRCW060310K0JNEBC)
R50  ValueDisplayed: 100k  [0603S]  (hidden comment: RC0603FR-07100KL)
R51  ValueDisplayed: 510  [0603S]  (hidden comment: RC0603JR-07510RL)
R52  ValueDisplayed: 100k  [0603S]  (hidden comment: RC0603FR-07100KL)
R53  value 10k  [FP-CRCW060310K0JNEBC_0603-MFG]  (hidden comment: CRCW060310K0JNEBC)
R54  value 10k  [FP-CRCW060310K0JNEBC_0603-MFG]  (hidden comment: CRCW060310K0JNEBC)
R55  ValueDisplayed: 33k  [0603S]  (hidden comment: RC0603JR-0733KL)
R56  ValueDisplayed: 4.7  [0805_HV]  (hidden comment: ERJ-6GEYJ4R7V)
R57  ValueDisplayed: 330  [0603S]  (hidden comment: RC0603JR-07330RL)
R58  ValueDisplayed: 1.00k  [0603S]  (hidden comment: RC0603FR-071KL)
R59  ValueDisplayed: 2.20k  [0603S]  (hidden comment: RC0603FR-072K2L)
R60  value 10k  [FP-CRCW060310K0JNEBC_0603-MFG]  (hidden comment: CRCW060310K0JNEBC)
R61  ValueDisplayed: 680  [0603S]  (hidden comment: RC0603JR-07680RL)
R62  ValueDisplayed: 680  [0603S]  (hidden comment: RC0603JR-07680RL)
T2  750510476  [Wurth_750510476]
TP18  S2751-46R  [Harwin_S2751-46R]  (no BOM)
TP19  S2751-46R  [Harwin_S2751-46R]  (no BOM)
TP20  S2751-46R  [Harwin_S2751-46R]  (no BOM)
TP21  S2751-46R  [Harwin_S2751-46R]  (no BOM)
TP22  S2751-46R  [Harwin_S2751-46R]  (no BOM)
TP23  S2751-46R  [Harwin_S2751-46R]  (no BOM)
TP24  S2751-46R  [Harwin_S2751-46R]  (no BOM)
TP25  S2751-46R  [Harwin_S2751-46R]  (no BOM)
TP26  S2751-46R  [Harwin_S2751-46R]  (no BOM)
TP27  S2751-46R  [Harwin_S2751-46R]  (no BOM)
TP28  S2751-46R  [Harwin_S2751-46R]  (no BOM)
U11  AFE031AIRGZT  [RGZ0048B]

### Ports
ADCIN (out), DAC_EN (in), INT (out), LED1_EN (in), LED2_EN (in), PLC_HRPWM1 (in), PLC_HRPWM2 (in), PLC_IND+ (in), PLC_IND- (in), SD_EN (in), SPI_CLK (in), SPI_CS (in), SPI_SIMO (in), SPI_SOMI (out), Vafe (in)

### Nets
GND: C80.1 C83.1 C88.2 C89.2 C90.2 C91.2 C92.1 C93.1 C94.1 C95.1 C96.1 C97.1 C98.1 C99.2 C100.2 C101.2 C102.2 C103.2 C104.1 C105.2 C106.2 D10.1 D11.2(A) D14.2(A) L6.1 R52.1 R53.1 R54.1 R59.1 R60.1 T2.4 TP18.1 TP19.1 TP20.1 U11.1(DGND) U11.12(AGND1) U11.29(AGND2) U11.34(E_TX_IN) U11.35(E_TX_CLK) U11.38(ZC_IN2) U11.39(ZC_IN1) U11.40(PA_GND2) U11.41(PA_GND1) U11.49(EP)
PGND: C69.1 C84.1 L4.1 R23.2 ; port PLC_IND+
String_PGND: C69.2 L4.2 R23.1 T2.7 ; port PLC_IND-
Vafe: C96.2 C97.2 C98.2 C99.1 C100.1 C101.1 D9.1(K) R50.2 U11.44(PA_VS2) U11.45(PA_VS1) ; port Vafe
VCC-3V3: C102.1 C103.1 C104.2 C105.1 C106.1 D13.1(K) R46.2 R47.2 R48.2 R49.2 R55.1 R61.2 R62.2 U11.2(DVDD) U11.11(AVDD1) U11.30(AVDD2)
ADCIN: R57.2 TP27.1 ; port ADCIN
DAC_EN: R53.2 U11.7(DAC) ; port DAC_EN
INT: R55.2 U11.9(INT) ; port INT
LED1_EN: D15.1(K) ; port LED1_EN
LED2_EN: D16.1(K) ; port LED2_EN
PA_IN: C82.1 U11.18(PA_IN)
PLC_HRPWM1: R30.2 TP22.1 ; port PLC_HRPWM1
PLC_HRPWM2: R38.2 TP23.1 ; port PLC_HRPWM2
SD_EN: R54.2 U11.8(SD) ; port SD_EN
SPI_CLK: R46.1 U11.3(SCLK) ; port SPI_CLK
SPI_CS: R49.1 U11.6(~{CS}) ; port SPI_CS
SPI_SIMO: R47.1 U11.4(DIN) ; port SPI_SIMO
SPI_SOMI: R48.1 U11.5(DOUT) ; port SPI_SOMI
TX_PGA_IN: C80.2 R39.2 TP21.1 U11.13(TX_PGA_IN)
TX_PGA_OUT: R51.2 TP24.1 U11.14(TX_PGA_OUT)
NetC81_1: C81.1 D10.2 R56.2 R58.2 T2.1 TP26.1
NetC81_2: C81.2 L3.2
NetC82_2: C82.2 C83.2 R51.1
NetC84_2: C84.2 T2.8
NetC85_1: C85.1 U11.22(RX_F_OUT)
NetC85_2: C85.2 U11.21(RX_PGA2_IN)
NetC86_1: C86.1 C91.1 L5.1 L6.2 R59.2
NetC86_2: C86.2 D13.2(A) D14.1(K) TP28.1 U11.27(RX_PGA1_IN)
NetC87_1: C87.1 R58.1
NetC87_2: C87.2 L5.2
NetC88_1: C88.1 R56.1
NetC89_1: C89.1 U11.23(RX_C2)
NetC90_1: C90.1 U11.24(RX_C1)
NetC92_2: C92.2 C93.2 U11.19(REF1)
NetC94_2: C94.2 C95.2 U11.28(REF2)
NetD9_2: D9.2(A) D11.1(K) L3.1 R50.1 R52.2 TP25.1 U11.42(PA_OUT2) U11.43(PA_OUT1)
NetD15_2: D15.2(A) R61.1
NetD16_2: D16.2(A) R62.1
NetR30_1: R30.1 U11.15(TX_F_IN1)
NetR38_1: R38.1 U11.16(TX_F_IN2)
NetR39_1: R39.1 U11.17(TX_F_OUT)
NetR57_1: R57.1 U11.20(RX_PGA2_OUT)
NetR60_2: R60.2 U11.46(PA_ISET)
NetT2_2: T2.2 T2.3
NetU11_25: U11.25(RX_F_IN) U11.26(RX_PGA1_OUT)

Not connected (* = marked no-connect by the designer): U11 10(TSENSE)* 31(E_RX_OUT)* 32(E_RX_IN)* 33(E_TX_OUT) 36(ZC_OUT2) 37(ZC_OUT1) 47(TX_FLAG)* 48(RX_FLAG)*

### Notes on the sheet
- AFE031

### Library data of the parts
C69 = CMP-0008996-2: CAP, CERM, 0.39 uF, 100 V, +/- 10%, X7R, 1206; Manufacturer: MuRata; PartNumber: GRM31MR71H394KA01L; TaMin_C: -55°C; Polarized: N; SizeAreaWB_mm2: 10.92; Value1: Unknown; U/M: EA; Value: 0.39uF; TaMax_C: 125°C; SizeZ_mm: 1.35; SizeX_mm: 3.2; SizeY_mm: 1.6; Value2: 50V; SizeArea_mm2: 5.12; Cap_F: 390nF; AEC Category: Q200
C80 C83 C93 C95 = CMP-0045719-1: 1000 pF ±10% 50V Ceramic Capacitor X7R 0603 (1608 Metric); Manufacturer: KEMET; AEC Qualified: No; SizeZ_mm: 0.95mm; TempCo: 15%; ValueDisplayed: 1000pF; Value: 1nF
C81 C101 C106 = CMP-0009015-2: CAP, CERM, 10 uF, 50 V, +/- 10%, X5R, AEC-Q200 Grade 1, 1206; Manufacturer: MuRata; TaMin_C: -55°C; Polarized: N; SizeAreaWB_mm2: 10.92; Value1: Unknown; U/M: EA; Value: 10uF; TaMax_C: 85°C; SizeZ_mm: 1.8; SizeX_mm: 3.2; SizeY_mm: 1.6; Cap_Case: 1206; SizeArea_mm2: 5.12; AEC Qualified: Y; Cap_F: 10µF; AEC Grade: 1; AEC Category: Q200
C82 = CMP-0089171-1: 3300pF ±5% 100V Ceramic Capacitor X7R 0603 (1608 Metric); Manufacturer: AVX Corporation; SizeZ_mm: 0.9mm; AEC Qualified: Yes; AEC Grade: Grade 1; TempCo: 15%
C84 = CMP-0008779-2: CAP, CERM, 1 uF, 100 V, +/- 10%, X7R, AEC-Q200 Grade 1, 1206; Manufacturer: TDK; TaMin_C: -55°C; ESR_ohm: 4.575m; Polarized: N; SizeAreaWB_mm2: 10.92; Value1: 0.004575 ohm; U/M: EA; Value: 1uF; TaMax_C: 125°C; SizeZ_mm: 1.8; SizeX_mm: 3.2; SizeY_mm: 1.6; SizeArea_mm2: 5.12; AEC Qualified: Y; Cap_F: 1µF; IRMS_A: 3.3964A; AEC Grade: 1; AEC Category: Q200
C85 = CMP-0007433-4: CAP, CERM, 0.01 uF, 50 V, +/- 10%, X7R, 0603; Manufacturer: MuRata; TaMin_C: -55°C; Polarized: N; SizeAreaWB_mm2: 4.68; Value1: Unknown; U/M: EA; Value: 0.01uF; TaMax_C: 125°C; SizeZ_mm: 1; SizeX_mm: 1.6; SizeY_mm: 0.8; Cap_Case: 0603; SizeArea_mm2: 1.28; AEC Category: Q200
C86 C99 C100 C102 C103 C105 = CMP-0750039-1: CAP, CERM, 0.01 µF, 50 V,+/- 10%, X7R, 0603; Manufacturer: Wurth Elektronik; Polarized: N; AEC Category: Q200; TaMax_C: 125°C; SizeAreaWB_mm2: 4.68; Value: 0.01uF; SizeArea_mm2: 1.28; SizeY_mm: 0.8; SizeZ_mm: 1; ValueDisplayed: 0.01µF; SizeX_mm: 1.6; U/M: EA; Cap_Case: 0603; TaMin_C: -55°C
C87 = CMP-0007192-4: CAP, CERM, 1800 pF, 50 V, +/- 5%, C0G/NP0, 0603; Manufacturer: MuRata; TaMin_C: -55°C; Polarized: N; SizeAreaWB_mm2: 4.68; Value1: Unknown; U/M: EA; Value: 1800pF; TaMax_C: 125°C; SizeZ_mm: 1; SizeX_mm: 1.6; SizeY_mm: 0.8; Cap_Case: 0603; SizeArea_mm2: 1.28; Cap_F: 1.8nF; AEC Category: Q200
C88 = CMP-0006764-4: CAP, CERM, 1000 pF, 50 V, +/- 10%, C0G/NP0, 0603; Manufacturer: AVX; TaMin_C: -55°C; ESR_ohm: 0.048; Polarized: N; SizeAreaWB_mm2: 4.68; Value1: 0.048 ohm; U/M: EA; Value: 1000pF; TaMax_C: 125°C; SizeZ_mm: 1; SizeX_mm: 1.6; SizeY_mm: 0.8; Cap_Case: 0603; SizeArea_mm2: 1.28; Cap_F: 1nF; AEC Category: Q200
C89 = CMP-0007164-4: CAP, CERM, 560 pF, 25 V, +/- 5%, C0G/NP0, 0603; Manufacturer: MuRata; TaMin_C: -55°C; Polarized: N; SizeAreaWB_mm2: 4.68; Value1: Unknown; U/M: EA; Value: 560pF; TaMax_C: 125°C; SizeZ_mm: 1; SizeX_mm: 1.6; SizeY_mm: 0.8; Cap_Case: 0603; SizeArea_mm2: 1.28; AEC Category: Q200
C90 = CMP-0007203-4: CAP, CERM, 270 pF, 50 V, +/- 5%, C0G/NP0, 0603; Manufacturer: MuRata; TaMin_C: -55°C; Polarized: N; SizeAreaWB_mm2: 4.68; Value1: Unknown; U/M: EA; Value: 270pF; TaMax_C: 125°C; SizeZ_mm: 1; SizeX_mm: 1.6; SizeY_mm: 0.8; Cap_Case: 0603; SizeArea_mm2: 1.28; AEC Category: Q200
C91 = CMP-0006729-4: CAP, CERM, 1200 pF, 100 V, +/- 5%, X7R, 0603; Manufacturer: AVX; TaMin_C: -55°C; ESR_ohm: 2.54d; Polarized: N; SizeAreaWB_mm2: 4.68; Value1: 0.254 ohm; U/M: EA; Value: 1200pF; TaMax_C: 125°C; SizeZ_mm: 1; SizeX_mm: 1.6; SizeY_mm: 0.8; Cap_Case: 0603; SizeArea_mm2: 1.28; AEC Category: Q200
C92 C94 = CMP-0122291-1: 1 µF ±10% 50V Ceramic Capacitor X7T 0603 (1608 Metric); Manufacturer: Murata; AEC Qualified: No; Cap_F: 1µF; SizeZ_mm: 1mm; TempCo: +22/-33%; Value: 1µF
C96 C97 C104 = CMP-0094779-1: as C48 on sheet TIDA-010949 Power Optimizer_Aux
C98 = CMP-0093976-1: Cap Ceramic 47uF 25V X7R 20% Pad SMD 2220 +125°C Automotive T/R; Manufacturer: TDK; TempCo: 0.15; AEC Grade: Grade 1; Cap_F: 47µF; Value: 47µF; Tolerance_%: 0.2%; SizeZ_mm: 2.8mm; AEC Qualified: Yes
D9 D11 D13 D14 = CMP-0028416-2: Diode, Schottky, 50 V, 3 A, SMA; Manufacturer: Diodes Inc.; SizeArea_mm2: 16.3228; Vf_V: 700mV; AEC Category: Q101; Vr_V: 50V; SizeY_mm: 2.92; SizeAreaWB_mm2: 37.3428; RJC_CperW: 25; SizeZ_mm: 2.87; Value: 50V; Green_REACh: Incomplete; Io_A: 3A; Green_Lifecycle: Not Set; Value2: 0.7V; TJmax_C: 125°C; SizeX_mm: 5.59
D10 = CMP-0085011-1: Diode, TVS, Bi, 22 V, 35.5 Vc, 400 W, 11.3 A, SMA (non-polarized); Manufacturer: Littelfuse; SizeY_mm: 2.575; Vc: 35.5V; SizeZ_mm: 2.65; Ipp: 11.3A; Vbr_Min: 24.4V; SizeAreaWB_mm2: 32.368125; RJA_CperW: 120; AEC Qualified: N; SizeX_mm: 5.075; Ppk: 400W; SizeArea_mm2: 13.068125; AEC Category: Q101; Vbr_Max: 26.9V
D15 = CMP-0002946-3: as D7 on sheet TIDA-010949 Power Optimizer_MCU
D16 = CMP-0002947-3: as D12 on sheet TIDA-010949 Power Optimizer_MCU
L3 = CMP-0058657-1: Inductor, Wirewound, Ferrite, 1 uH, 0.595 A, 0.25 ohm, SMD; Manufacturer: MuRata; Irms: 0.595A @ 40C rise; Green_Lifecycle: Active; SizeAreaWB_mm2: 7.8; DCR_ohm: 2.5d; Green_REACh: Passed; Value: 1uH; Imax_A: 5.95dA; SizeZ_mm: 0.7; SizeX_mm: 2; SizeY_mm: 1.6; Value2: 0.595A; SizeArea_mm2: 3.2; Ind_H: 1µH; AEC Category: Q200
L4 = CMP-0060824-1: Inductor, Shielded E Core, Ferrite, 3.6 uH, 25 A, 0.0017 ohm, SMD; Manufacturer: Coilcraft; Isat: 25A @ 10% inductance drop; Irms: 30A @ 40C rise; Green_Lifecycle: Not Set; SizeAreaWB_mm2: 438.426; DCR_ohm: 1.7m; Green_REACh: Incomplete; Value: 3.6uH; Imax_A: 25A; SizeZ_mm: 12.95; SizeX_mm: 19.18; SizeY_mm: 18.7; SizeArea_mm2: 358.666; Ind_H: 3.6µH; AEC Category: Q200
L5 = CMP-0061680-2: Inductor, Drum Core, Ferrite, 1 mH, 0.1 A, 19 ohm, SMD; Manufacturer: Coilcraft; Isat: 0.1A @ 10% inductance drop; Irms: 0.15A @ 40C rise; Green_Lifecycle: Not Set; SizeAreaWB_mm2: 55.47; DCR_ohm: 19; Green_REACh: Incomplete; Value1: 19 ohm; Value: 1mH; Imax_A: 100mA; SizeZ_mm: 2.49; SizeX_mm: 6.6; SizeY_mm: 4.45; Value2: 0.1A; SizeArea_mm2: 29.37; AEC Category: Q200
L6 = CMP-0061972-2: Inductor, Drum Core, Ferrite, 1.5 mH, 0.08 A, 21 ohm, SMD; Manufacturer: Coilcraft; Isat: 0.075A @ 10% inductance drop; Irms: 0.14A @ 40C rise; Green_Lifecycle: Not Set; SizeAreaWB_mm2: 55.47; DCR_ohm: 21; Green_REACh: Incomplete; Value1: 21 ohm; Value: 1.5mH; Imax_A: 80mA; SizeZ_mm: 2.49; SizeX_mm: 6.6; SizeY_mm: 4.45; Value2: 0.08A; SizeArea_mm2: 29.37; AEC Category: Q200
R23 = CMP-0083579-1: RES, 5.6, 5%, 0.5 W, 1210; Manufacturer: Yageo; Power_W: 500mW; TempCo: 200 ppm/C; SizeAreaWB_mm2: 14.7; Value_Code: 5R60; Value: 5.6; EIA_Code: E24; SizeX_mm: 3.2; SizeY_mm: 2.5; SizeZ_mm: 1.35; Value2: 0.5W; SizeArea_mm2: 8; AEC Qualified: N; VDC_V: 200V; AEC Category: Q200
R30 R38 = CMP-0025923-5: RES, 43 k, 5%, 0.1 W, 0603; Manufacturer: Yageo; Power_W: 100mW; TempCo: 100 ppm/C; Value_Code: 43k0; Value: 43k; EIA_Code: E24; SizeX_mm: 1.6; SizeY_mm: 0.8; SizeZ_mm: 1; Value2: 0.1W; SizeArea_mm2: 1.28; AEC Qualified: N; VDC_V: 75V; AEC Category: Q200; SizeAreaWB_mm2: 4.68
R39 R51 = CMP-0025928-5: RES, 510, 5%, 0.1 W, 0603; Manufacturer: Yageo; Power_W: 100mW; TempCo: 100 ppm/C; Value_Code: 510R; Value: 510; EIA_Code: E24; SizeX_mm: 1.6; SizeY_mm: 0.8; SizeZ_mm: 1; Value2: 0.1W; SizeArea_mm2: 1.28; AEC Qualified: N; VDC_V: 75V; AEC Category: Q200; SizeAreaWB_mm2: 4.68
R46-R49 R53 R54 R60 = CMP-0098286-1: 10 kOhms ±5% 0.1W, 1/10W Chip Resistor 0603 (1608 Metric) Thick Film; Manufacturer: Vishay; AEC Qualified: No; Power_W: 100mW; SizeZ_mm: 0.55mm; TempCo: 200ppm/°C; VDC_V: 75V
R50 R52 = CMP-0022735-5: RES, 100 k, 1%, 0.1 W, 0603; Manufacturer: Yageo; Power_W: 100mW; TempCo: 100 ppm/C; Value: 100k; EIA_Code: E96; SizeX_mm: 1.6; SizeY_mm: 0.8; SizeZ_mm: 1; Value2: 0.1W; SizeArea_mm2: 1.28; AEC Qualified: N; VDC_V: 75V; AEC Category: Q200; SizeAreaWB_mm2: 4.68
R55 = CMP-0025913-5: RES, 33 k, 5%, 0.1 W, 0603; Manufacturer: Yageo; Power_W: 100mW; TempCo: 100 ppm/C; Value_Code: 33k0; Value: 33k; EIA_Code: E24; SizeX_mm: 1.6; SizeY_mm: 0.8; SizeZ_mm: 1; Value2: 0.1W; SizeArea_mm2: 1.28; AEC Qualified: N; VDC_V: 75V; AEC Category: Q200; SizeAreaWB_mm2: 4.68
R56 = CMP-0020737-3: RES, 4.7, 5%, 0.125 W, AEC-Q200 Grade 0, 0805; Manufacturer: Panasonic; Power_W: 125mW; TempCo: 600 ppm/C; Value_Code: 4R70; Value: 4.7; EIA_Code: E24; SizeX_mm: 2; SizeY_mm: 1.25; SizeZ_mm: 1.45; Value2: 0.125W; SizeArea_mm2: 2.5; AEC Qualified: Y; VDC_V: 150V; AEC Category: Q200; AEC Grade: 0; SizeAreaWB_mm2: 6.75
R57 = CMP-0025912-5: RES, 330, 5%, 0.1 W, 0603; Manufacturer: Yageo; Power_W: 100mW; TempCo: 100 ppm/C; Value_Code: 330R; Value: 330; EIA_Code: E24; SizeX_mm: 1.6; SizeY_mm: 0.8; SizeZ_mm: 1; Value2: 0.1W; SizeArea_mm2: 1.28; AEC Qualified: N; VDC_V: 75V; AEC Category: Q200; SizeAreaWB_mm2: 4.68
R58 = CMP-0022895-5: as R16 on sheet TIDA-010949 Power Optimizer_Aux
R59 = CMP-0022986-5: RES, 2.20 k, 1%, 0.1 W, 0603; Manufacturer: Yageo; Power_W: 100mW; TempCo: 100 ppm/C; Value_Code: 2k20; Value: 2.20k; Res_ohm: 2.2k; SizeX_mm: 1.6; SizeY_mm: 0.8; SizeZ_mm: 1; Value2: 0.1W; SizeArea_mm2: 1.28; AEC Qualified: N; VDC_V: 75V; AEC Category: Q200; SizeAreaWB_mm2: 4.68
R61 R62 = CMP-0025936-5: as R29 on sheet TIDA-010949 Power Optimizer_MCU
T2 = CMP-0030703-1: Transformer, 870uH. TH; Manufacturer: Wurth Elektronik; LeakageInd_H: 400nH; Value: 870uH; Ind_H: 870µH; Lp: 870; DCR_ohm: 45m
TP18-TP28 = CMP-0003968-1: Test Point, SMT; Manufacturer: Harwin
U11 = CMP-0040436-2: Powerline Communications Analog Front End, 7 to 26 V, -40 to 125 degC, 48-pin QFN (RGZ48), Green (RoHS & no Sb/Br); Manufacturer: Texas Instruments; Packing: SMALL T&R; Slew Rate(Typ)(V/us): 19; Rating: Catalog; Total Supply Voltage(Max)(+5V is 5, +/-5V is 10): 26; GBW(Typ)(MHz): 4.4; Iq per channel(Max)(mA): 60.3; Total Supply Voltage(Min)(+5V is 5, +/-5V is 10): 7; Sub Family: Precision Amplifier; SizeAreaWB_mm2: 81; SizeArea_mm2: 49; SizeZ_mm: 1

## Sheet TIDA-010949 Power Optimizer_Wireless.SchDoc
size 431 x 279 mm; Date: Not shown in title block; ApprovedBy: Not shown in title block; CheckedBy: Not shown in title block; Author: Not shown in title block; CompanyName: Not shown in title block; Engineer: Not shown in title block; Organization: Not shown in title block; Address1: Not shown in title block; Address2: Not shown in title block; Address3: Not shown in title block; Address4: Not shown in title block; DocumentNumber: 2; Revision: Use project parameter SCH_Rev; SheetNumber: 7; SheetTotal: 8; PageSetup: Record=PageOptions¦CenterHorizontal=True¦CenterVertical=True¦PrintScale=1.00¦XCorrection=1.00¦YCorrection=1.00¦PrintKind=0¦BorderSize=5000000¦LeftOffset=0¦BottomOffset=0¦Orientation=2¦PaperLength=1000¦PaperWidth=1000¦Scale=100¦PaperSource=15¦PrintQuality=600¦MediaType=1¦DitherType=10¦PaperKind=Letter¦PrintScaleMode=1
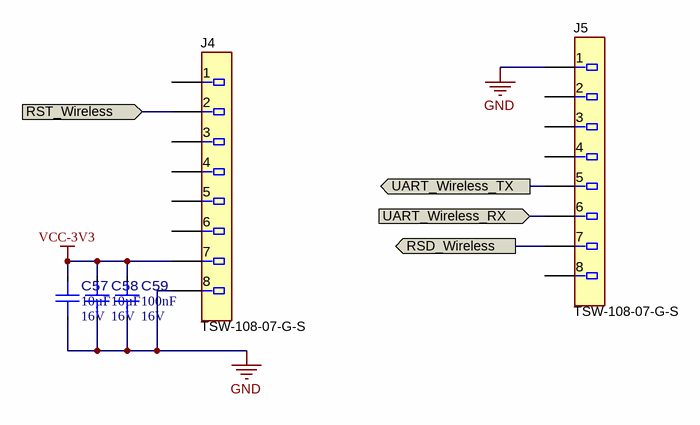
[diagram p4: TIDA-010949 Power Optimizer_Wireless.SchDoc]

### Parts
C57  Cap_F: 10µF  VDC_V: 16V  [FP-0805YC106KAT2A_0805-MFG]  (hidden comment: 0805YC106KAT2A)
C58  Cap_F: 10µF  VDC_V: 16V  [FP-0805YC106KAT2A_0805-MFG]  (hidden comment: 0805YC106KAT2A)
C59  Cap_F: 100nF  VDC_V: 16V  [FP-GCJ188R71C104KA01D_0603-MFG]  (hidden comment: GCJ188R71C104KA01D)
J4  TSW-108-07-G-S  [TSW-108-07-G-S]
J5  TSW-108-07-G-S  [TSW-108-07-G-S]

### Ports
RSD_Wireless (out), RST_Wireless (in), UART_Wireless_RX (in), UART_Wireless_TX (out)

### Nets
GND: C57.1 C58.1 C59.1 J4.8 J5.1
VCC-3V3: C57.2 C58.2 C59.2 J4.7
RSD_MCU: J5.7 ; port RSD_Wireless
RST_MCU: J4.2 ; port RST_Wireless
UART_RX: J5.5 ; port UART_Wireless_TX
UART_TX: J5.6 ; port UART_Wireless_RX

Not connected (* = marked no-connect by the designer): J4 1 3 4 5 6; J5 2 3 4 8

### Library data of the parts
C57 C58 = CMP-0121608-1: 10 µF ±10% 16V Ceramic Capacitor X7R 0805 (2012 Metric); Manufacturer: Kyocera AVX; AEC Qualified: No; SizeZ_mm: 0.75mm; TempCo: 15%; ValueDisplayed: 10uF; Value: 10µF
C59 = CMP-0090409-1: 0.1µF ±10% 16V Ceramic Capacitor X7R 0603 (1608 Metric); Manufacturer: Murata Electronics North America; AEC Grade: Grade 1; ValueDisplayed: 0.1uF; AEC Qualified: Yes; SizeZ_mm: 0.9mm; TempCo: 15%; Value: 100nF
J4 J5 = CMP-0075419-2: Header, 100mil, 8x1, Gold, TH; Manufacturer: Samtec; Green_REACh: Passed; Cert_CSA: Y; Shrouded: N; Voltage_V: 550V; CNHeader: True; Row_Count: 1; Gender: Male; CT: False; Current_A: 6.3A; Green_Lifecycle: Active; Pitch_mm: 2.54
